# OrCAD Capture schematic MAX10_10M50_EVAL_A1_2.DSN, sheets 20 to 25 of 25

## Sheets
20 Hot Swap and Power 3.3 V: size A3
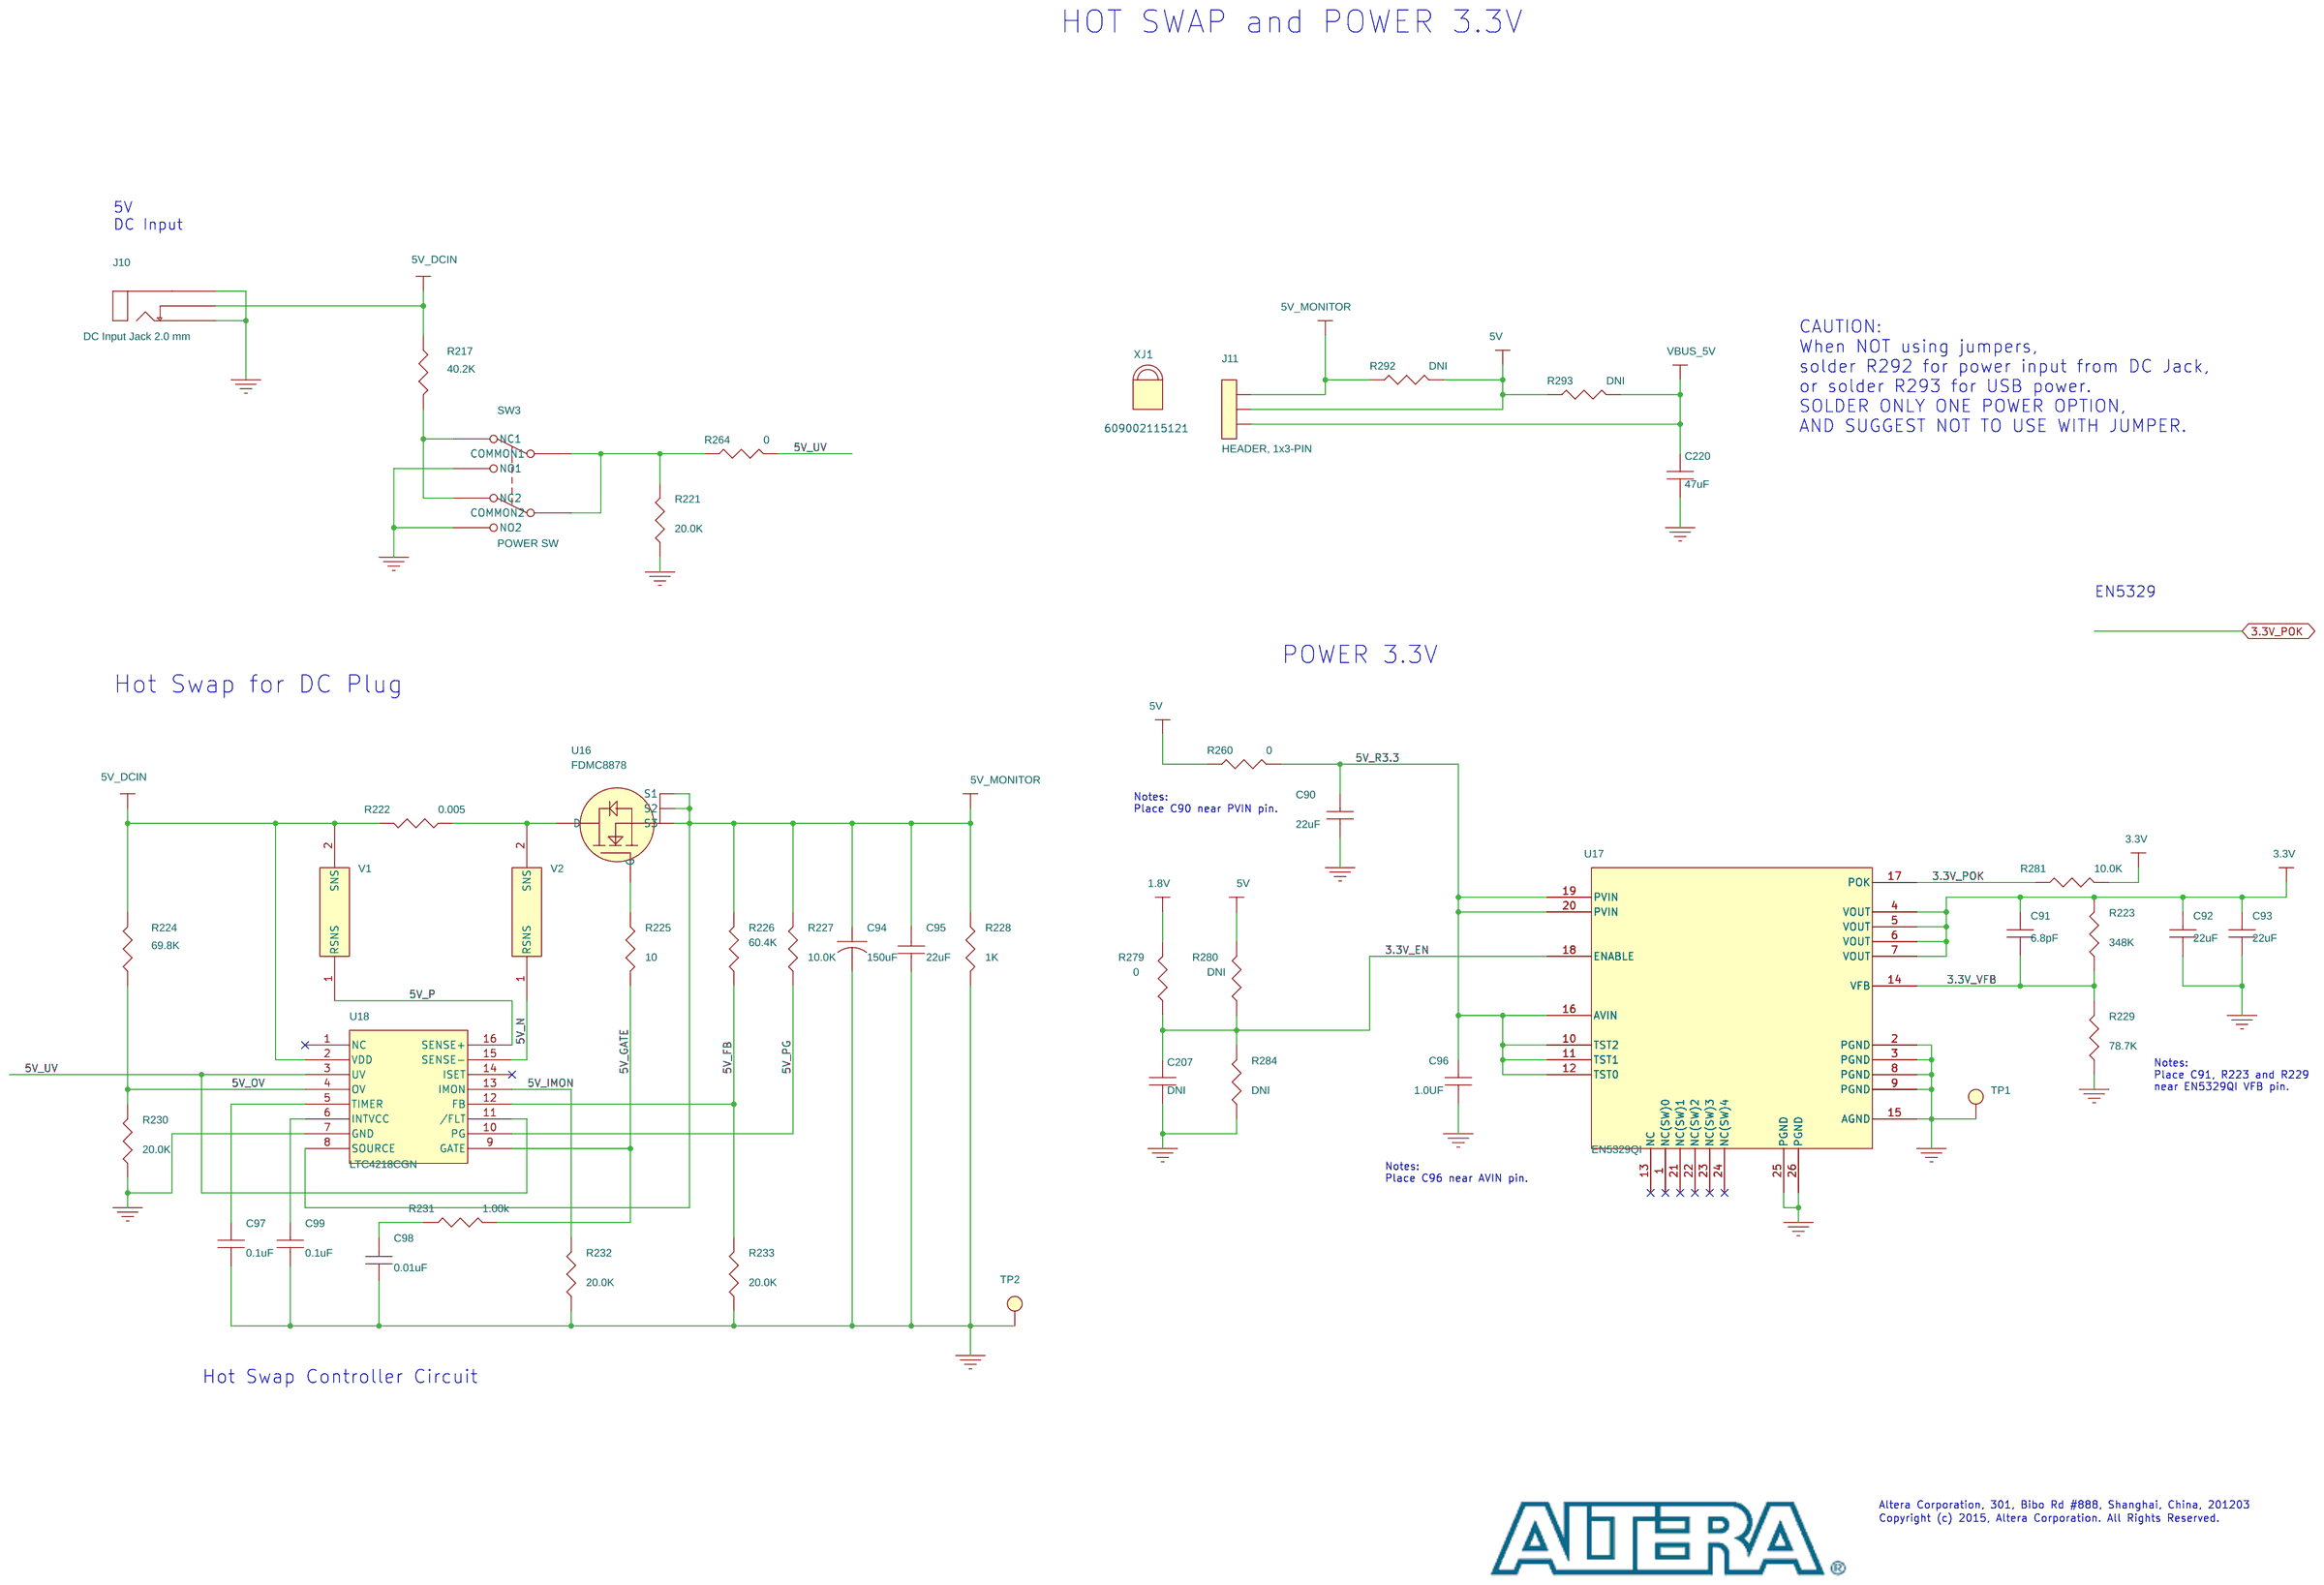
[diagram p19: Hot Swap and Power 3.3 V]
21 Power 2.5 V & 1.8V: size A3
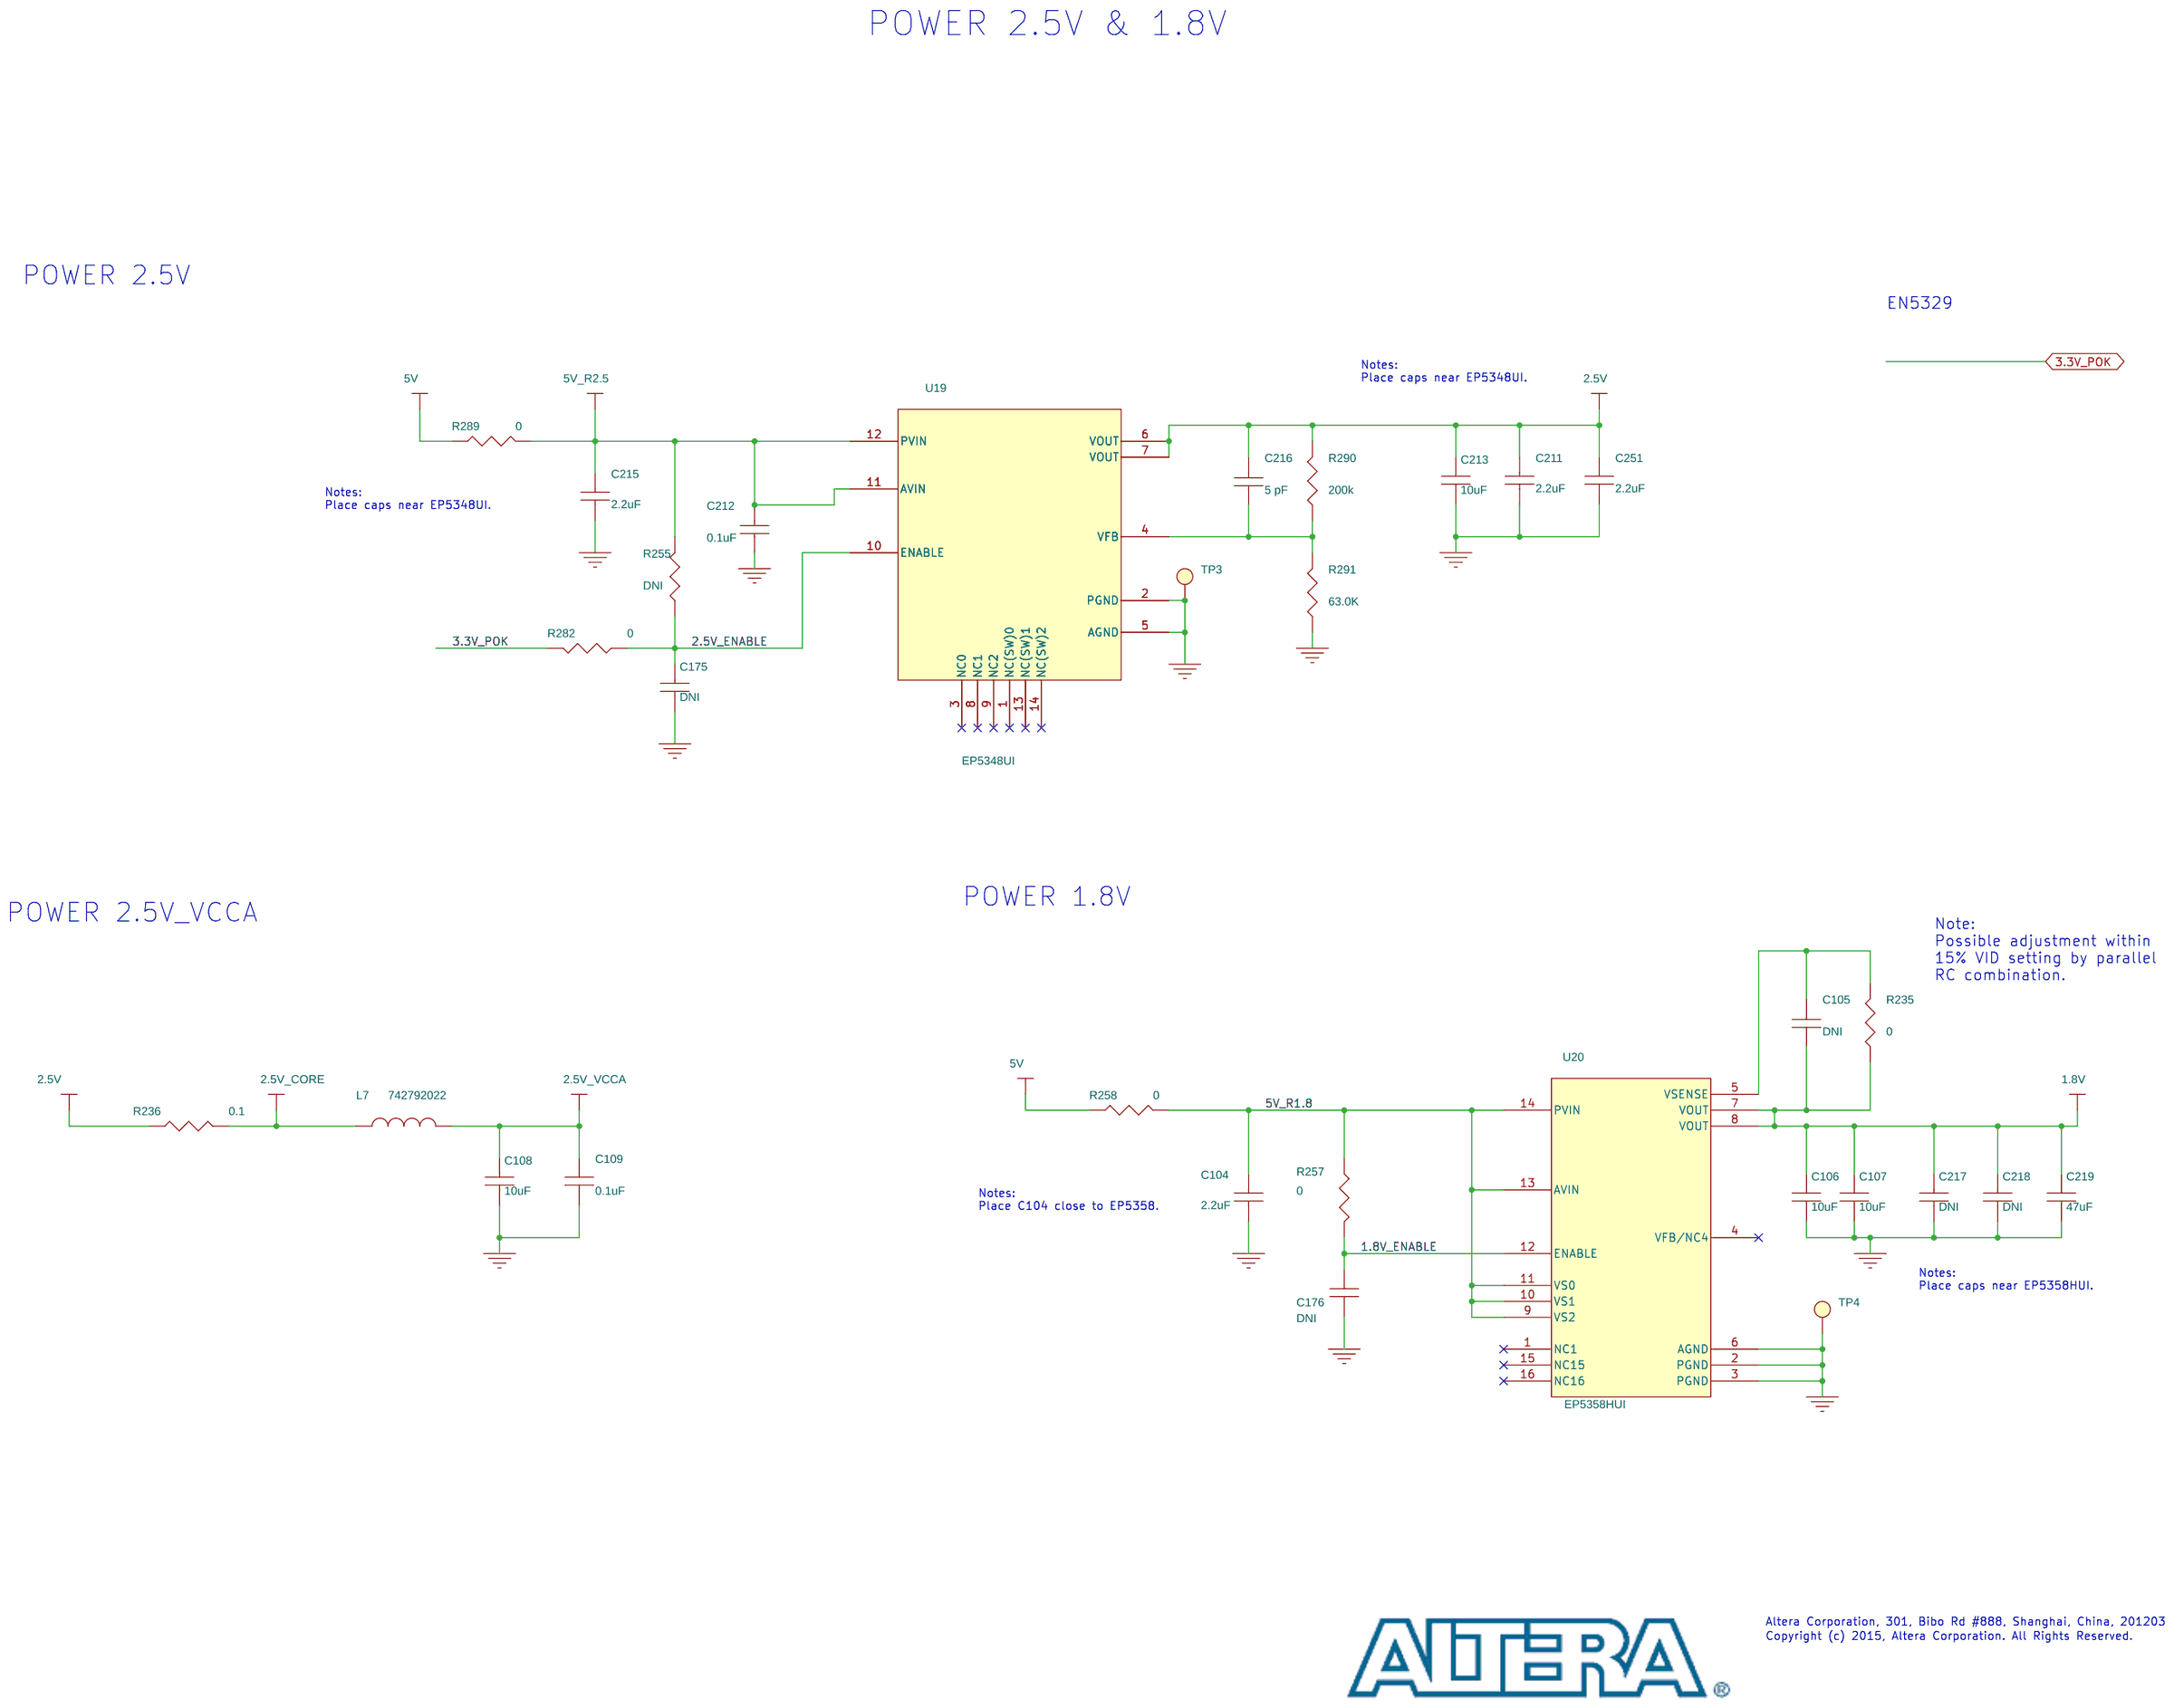
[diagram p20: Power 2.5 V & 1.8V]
22 Power 1.2V: size A3
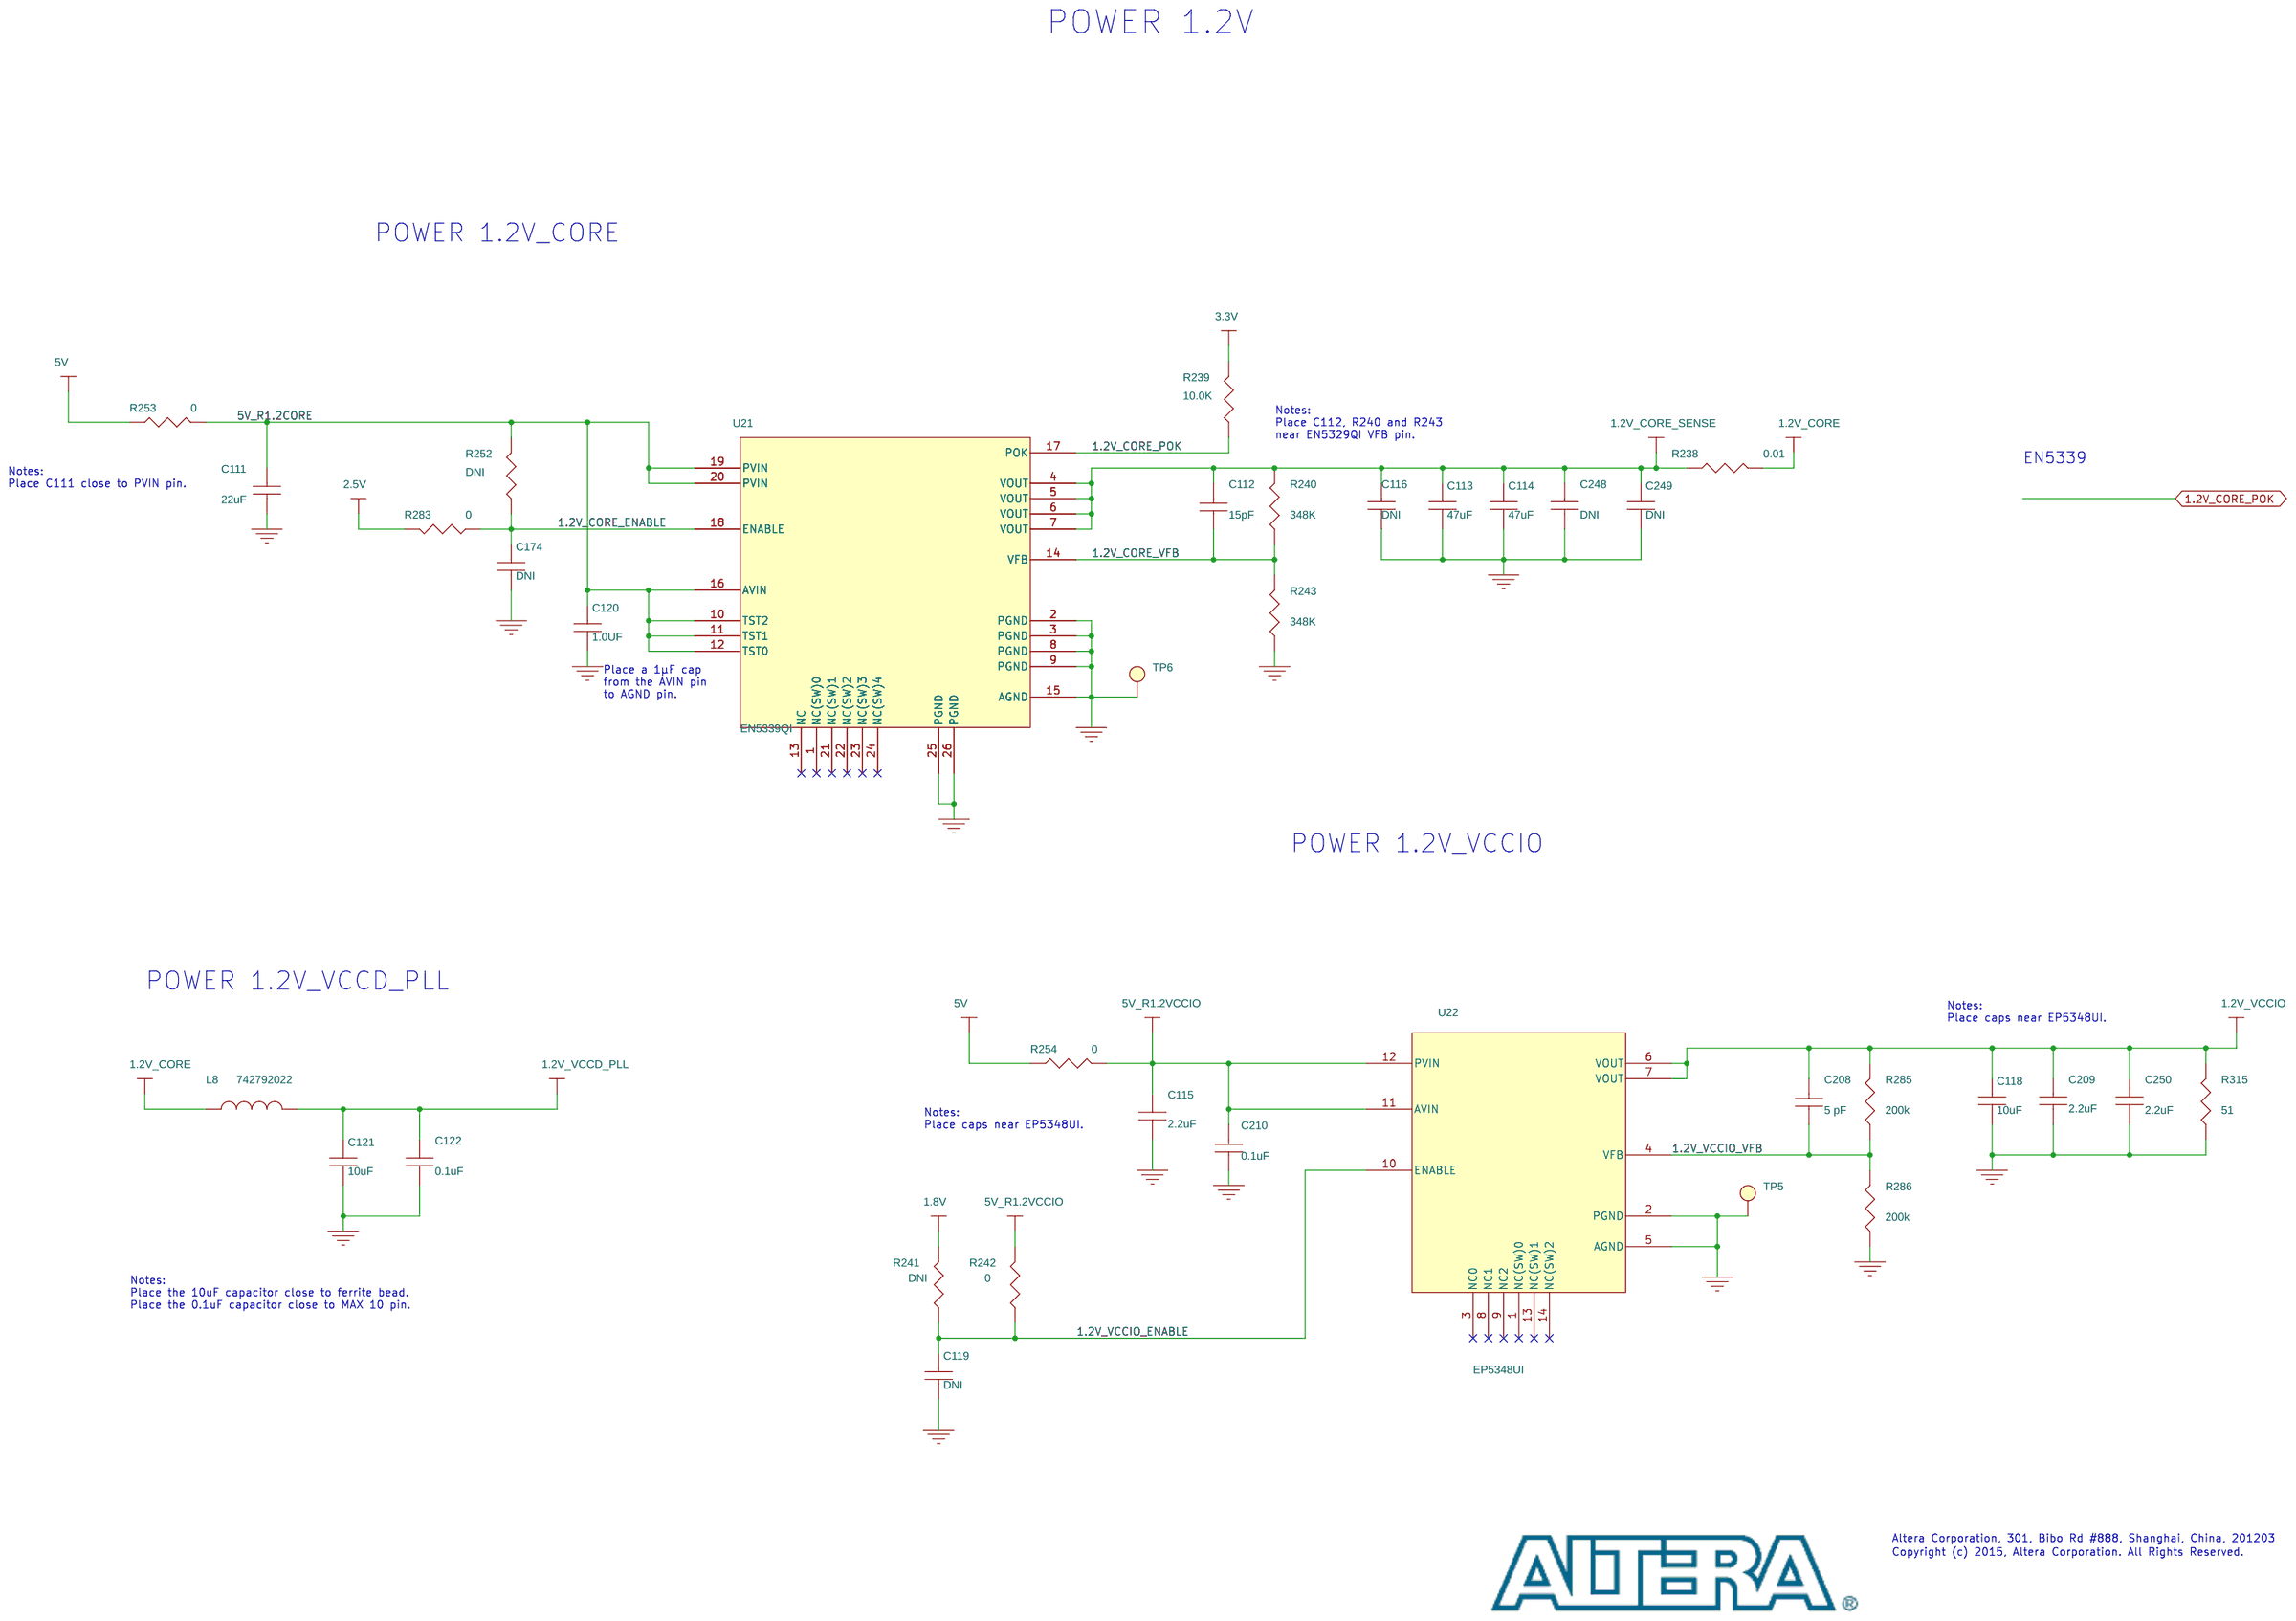
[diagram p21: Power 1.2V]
23 MAX 10 Power & Ground: size A3
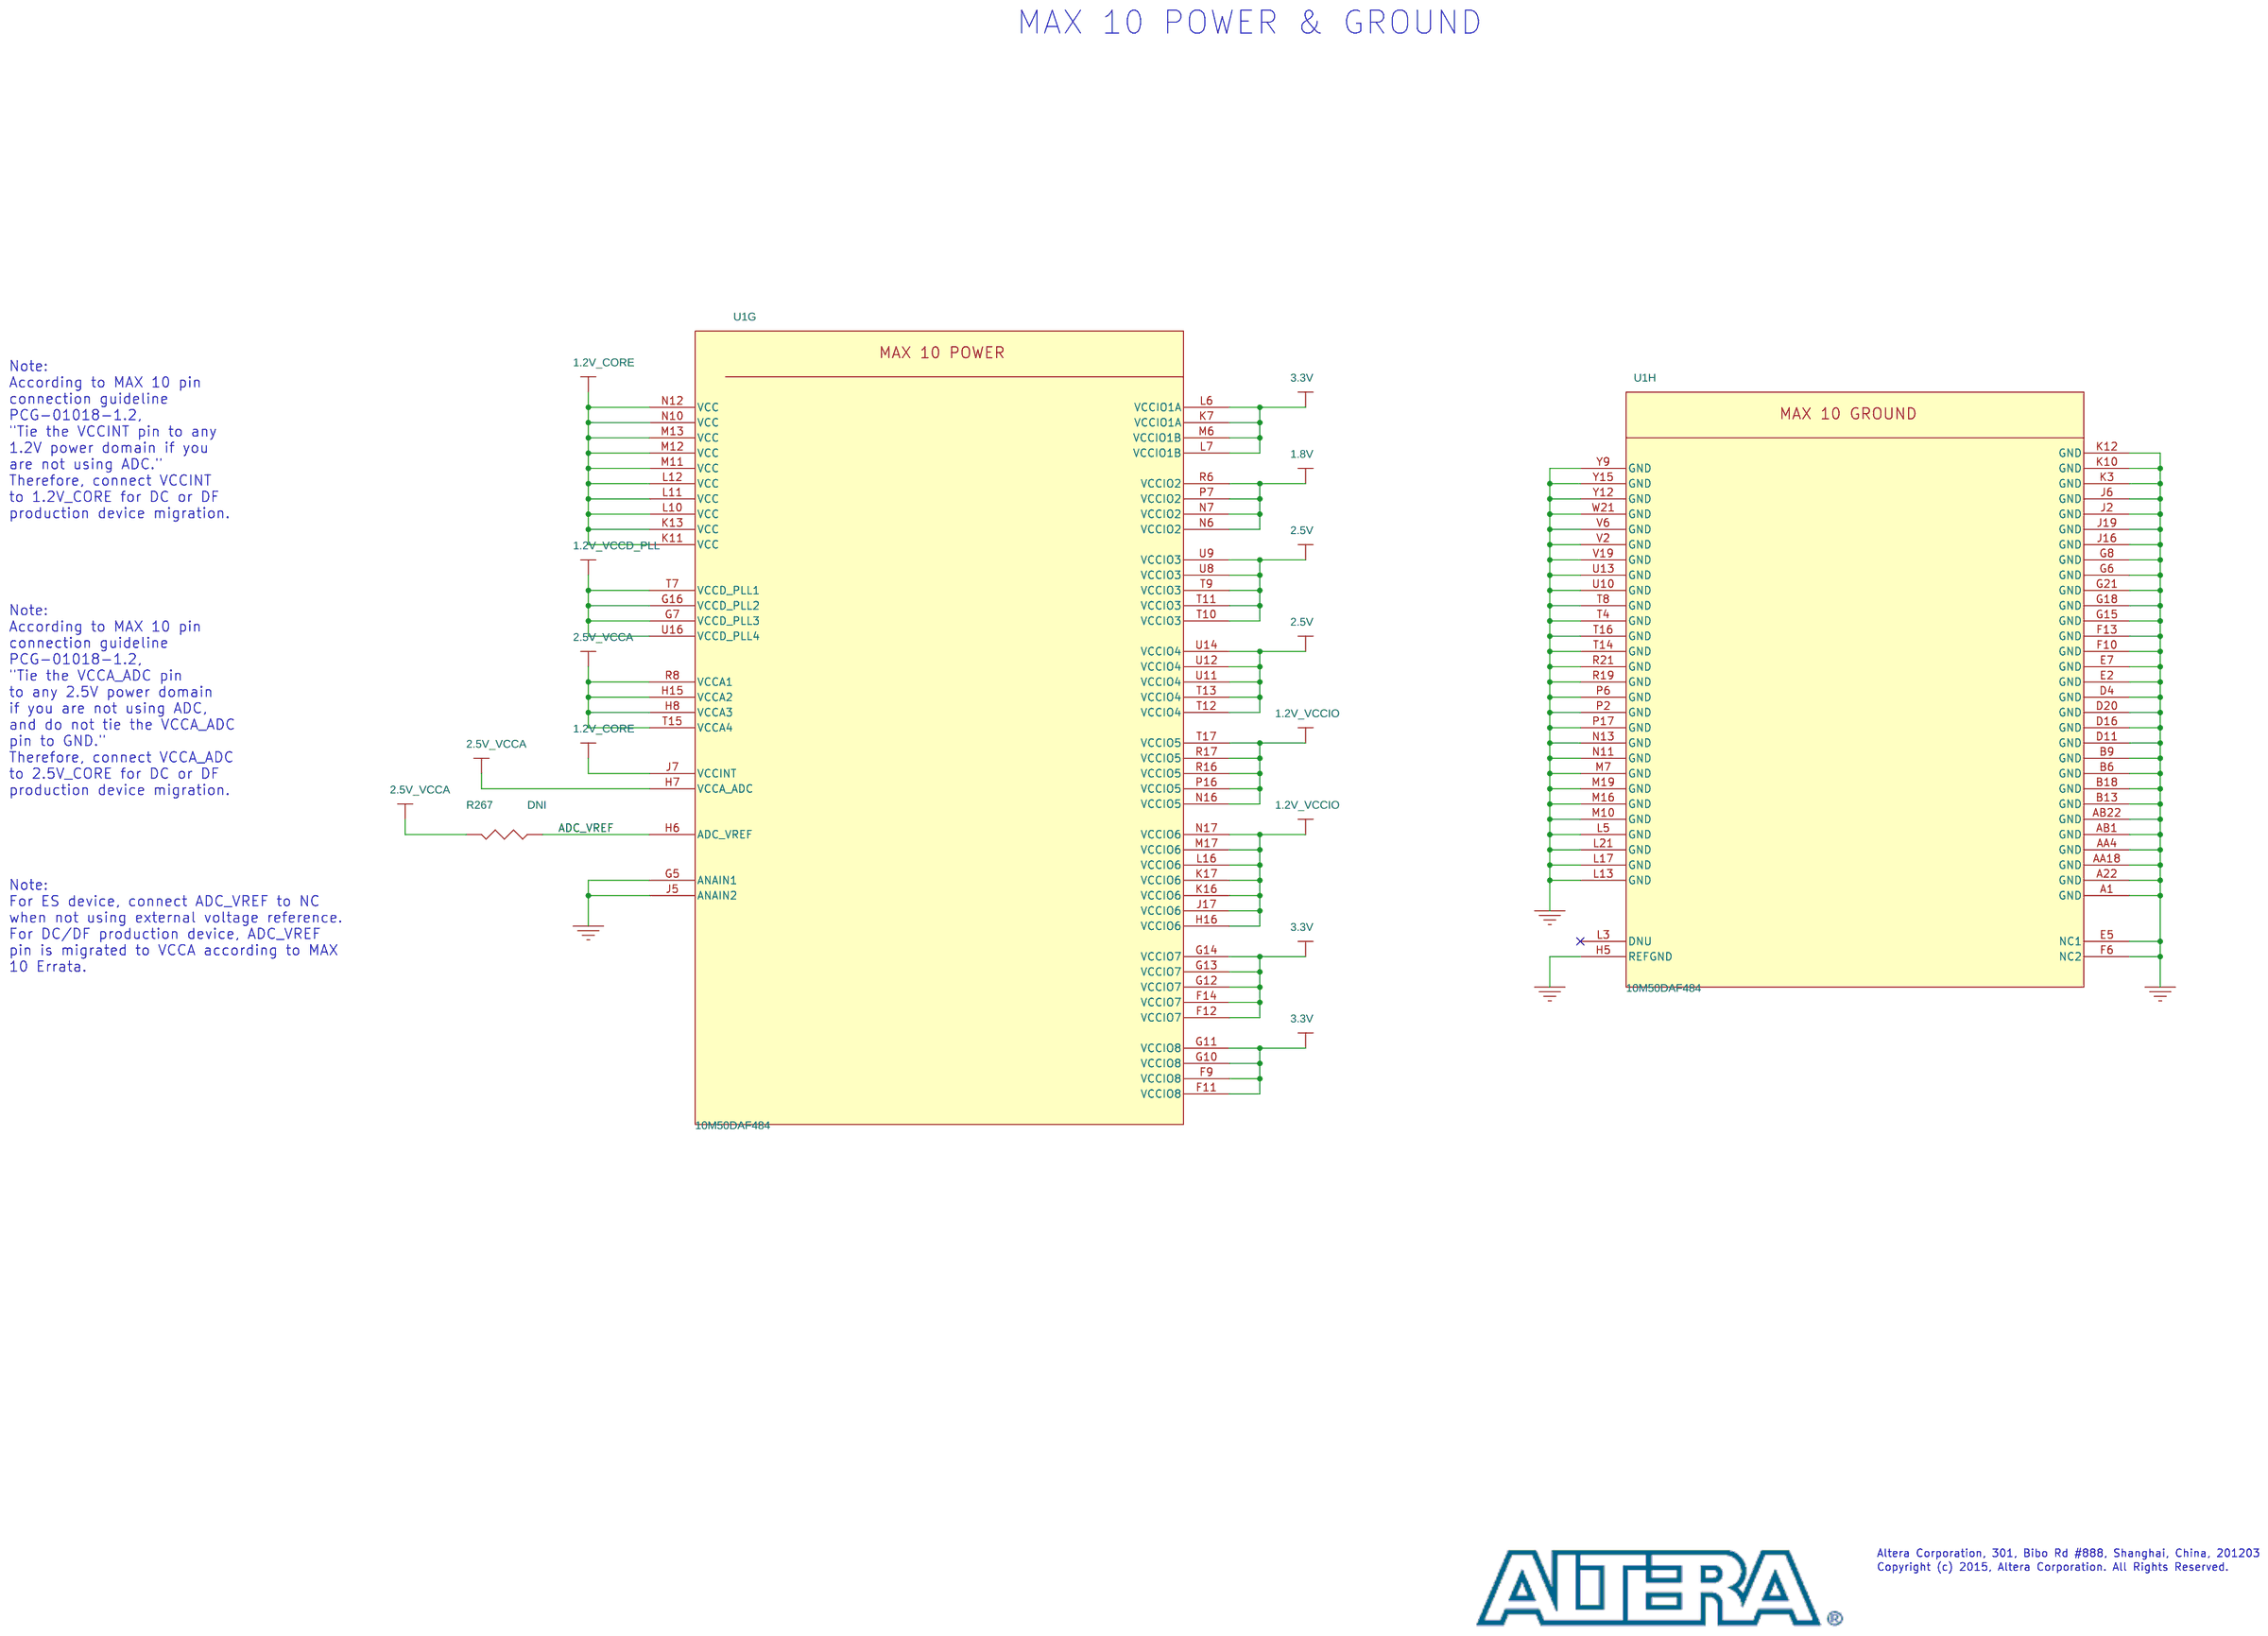
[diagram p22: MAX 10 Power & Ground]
24 Decoupling: size A3
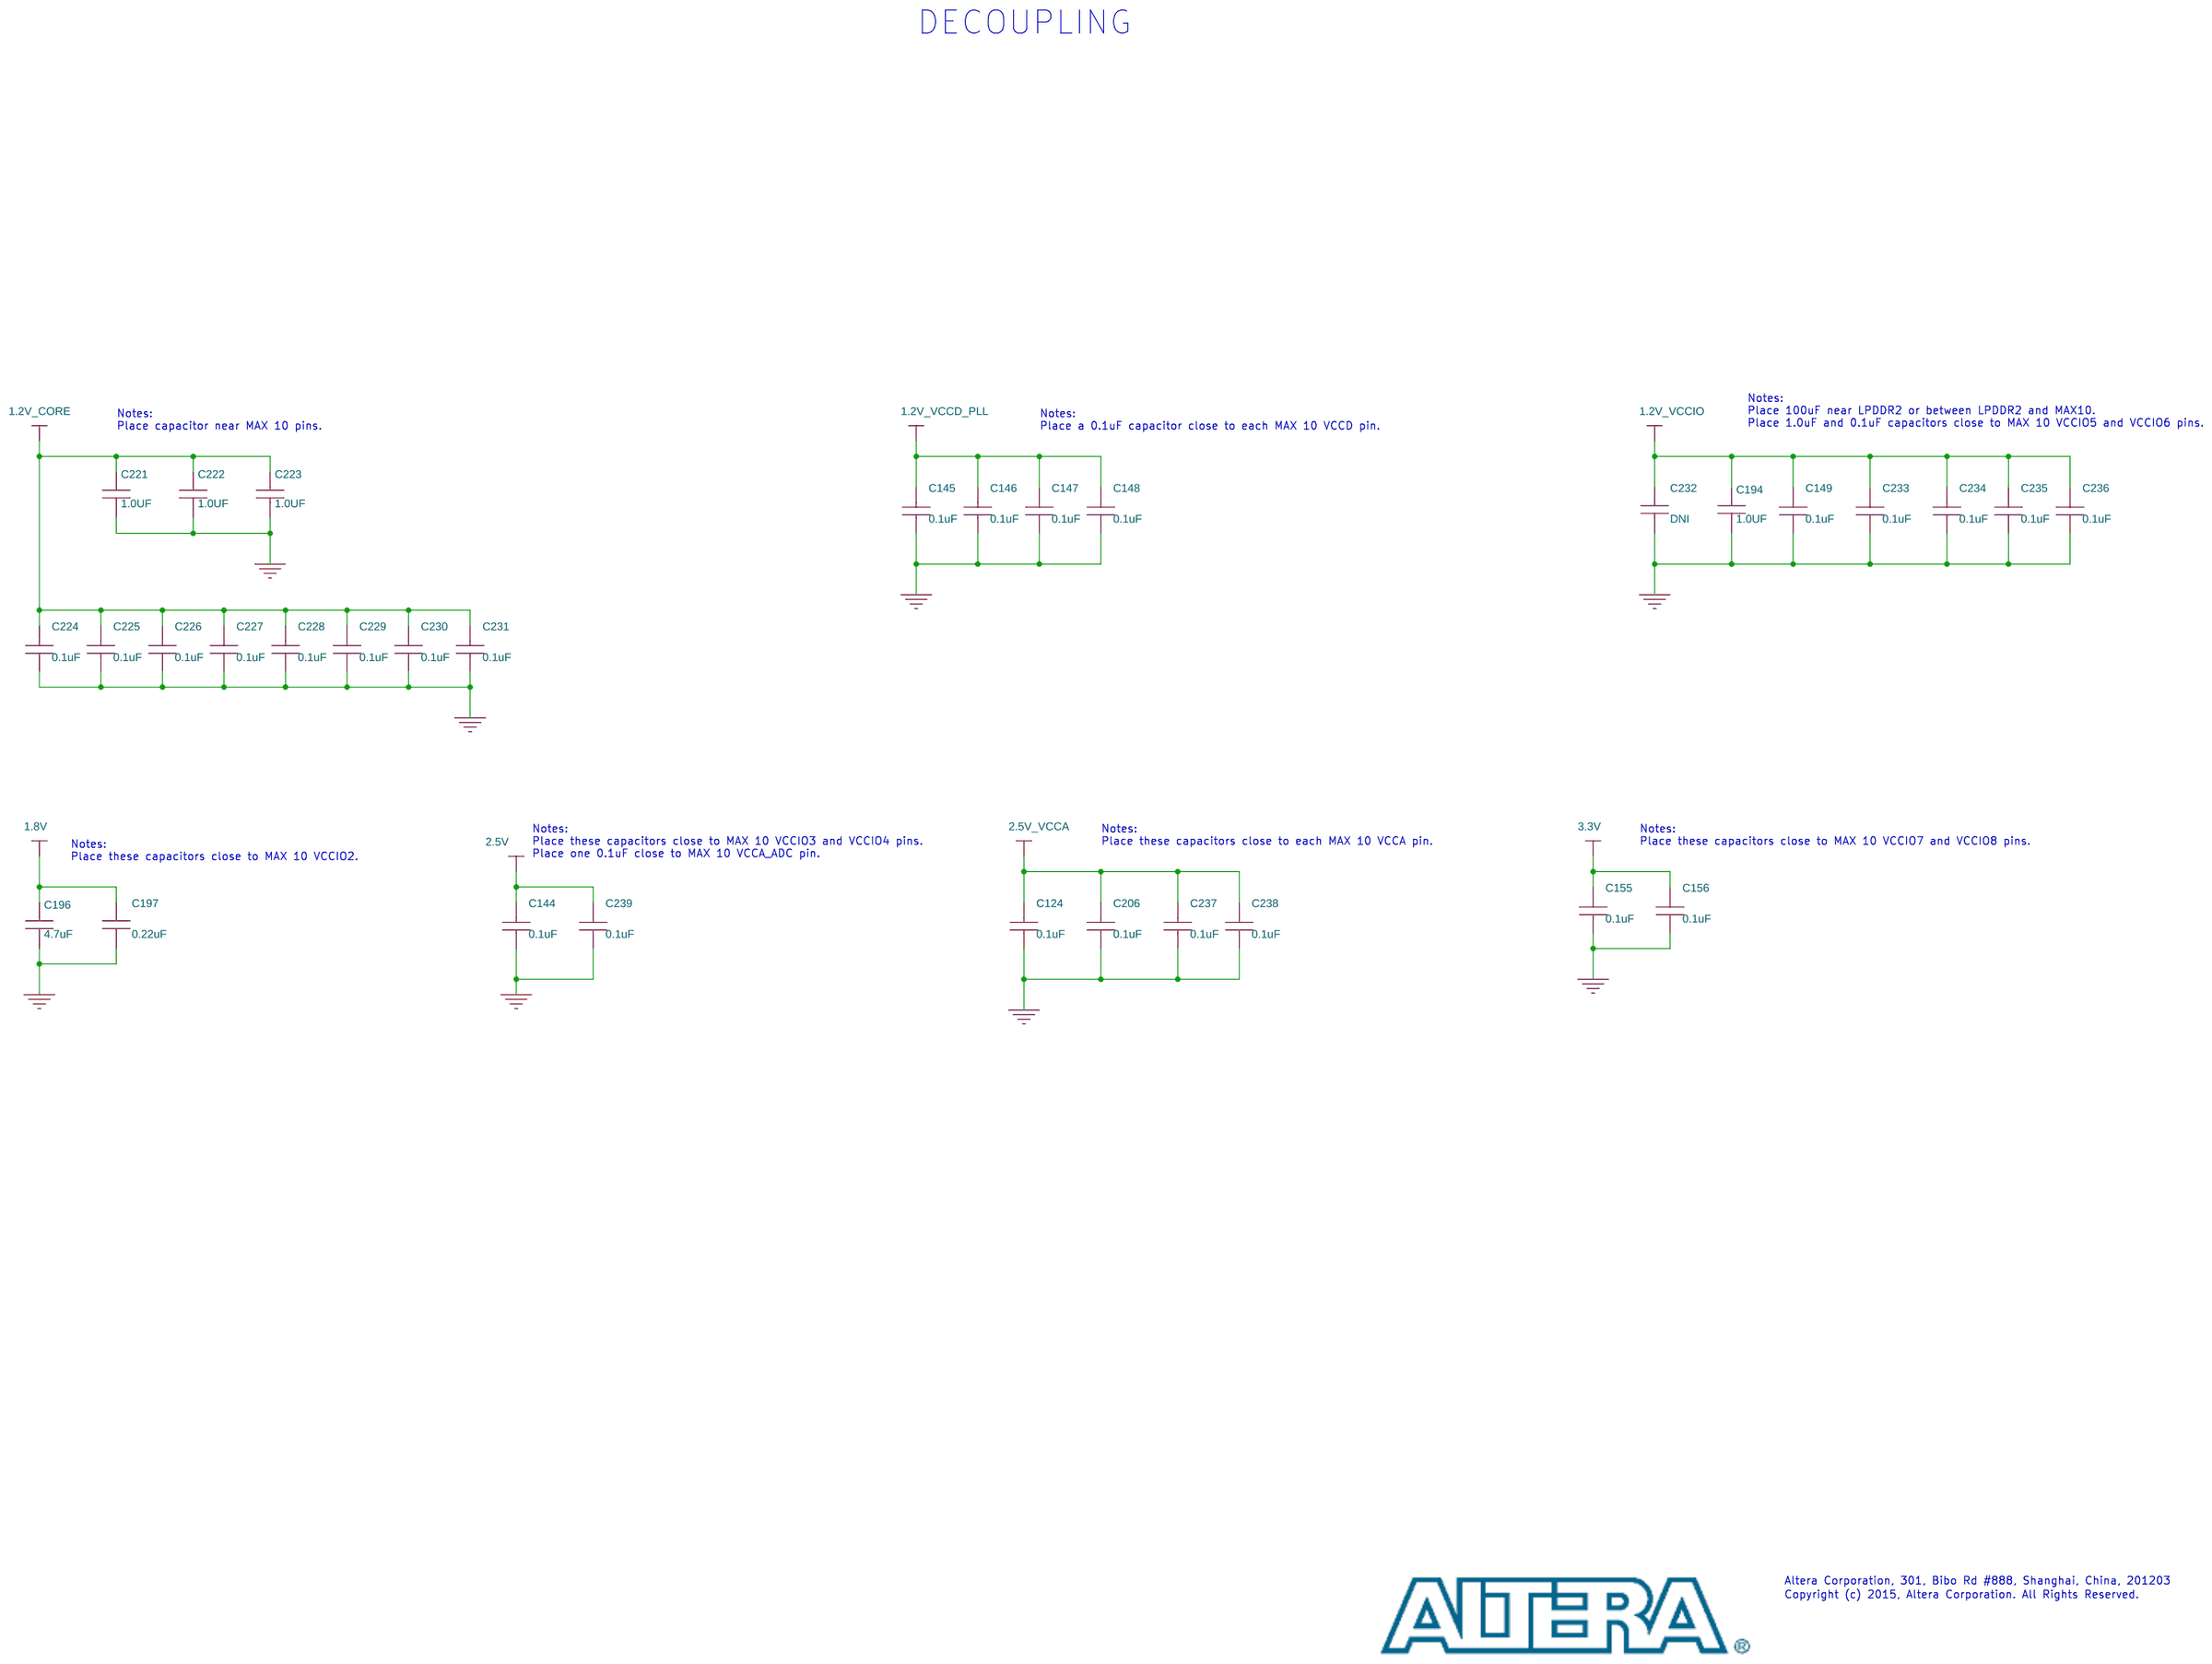
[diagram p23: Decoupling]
25 QSPI Flash: size A3
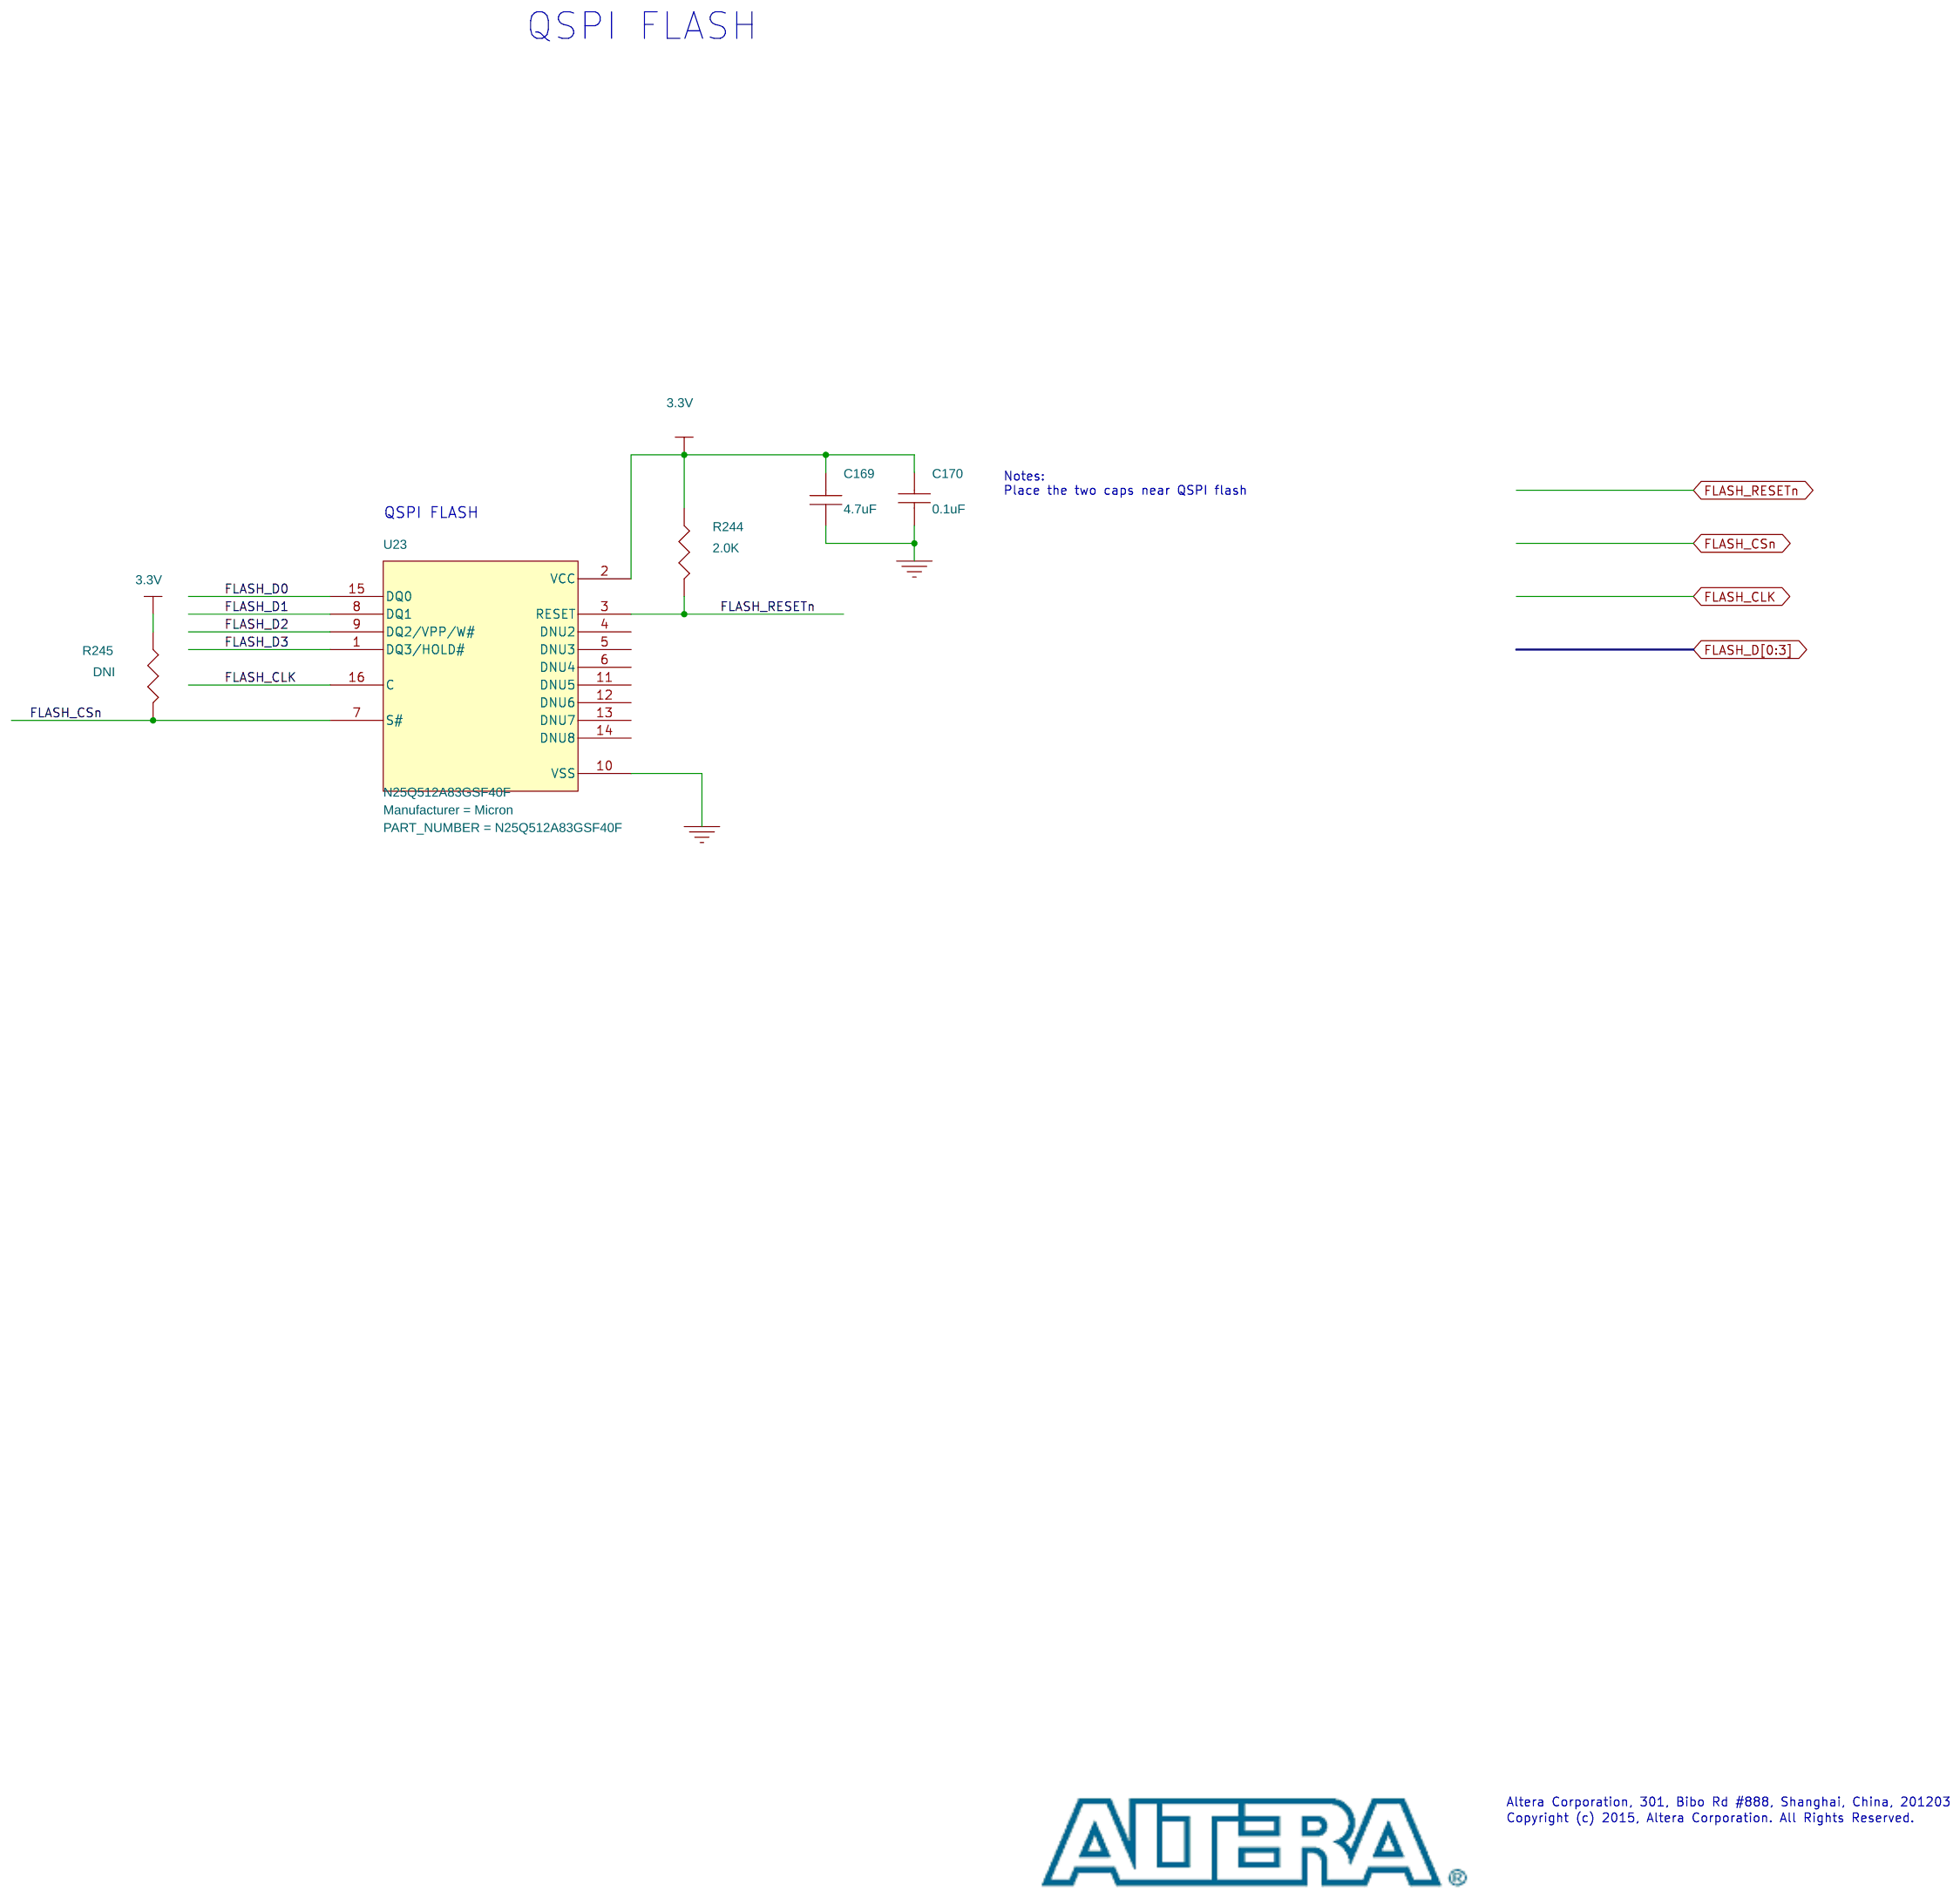
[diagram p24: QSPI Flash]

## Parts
sheet Decoupling
C124  0.1uF  [C0402_BGA]
C144  0.1uF  [C0402_BGA]
C145  0.1uF  [C0402_BGA]
C146  0.1uF  [C0402_BGA]
C147  0.1uF  [C0402_BGA]
C148  0.1uF  [C0402_BGA]
C149  0.1uF  [C0402_BGA]
C155  0.1uF  [C0402_BGA]
C156  0.1uF  [C0402_BGA]
C194  1.0UF  [C0402_BGA]
C196  4.7uF  [C0402_BGA]
C197  0.22uF  [0402]
C206  0.1uF  [C0402_BGA]
C221  1.0UF  [C0402_BGA]
C222  1.0UF  [C0402_BGA]
C223  1.0UF  [C0402_BGA]
C224  0.1uF  [C0402_BGA]
C225  0.1uF  [C0402_BGA]
C226  0.1uF  [C0402_BGA]
C227  0.1uF  [C0402_BGA]
C228  0.1uF  [C0402_BGA]
C229  0.1uF  [C0402_BGA]
C230  0.1uF  [C0402_BGA]
C231  0.1uF  [C0402_BGA]
C232  DNI  [1210]
C233  0.1uF  [C0402_BGA]
C234  0.1uF  [C0402_BGA]
C235  0.1uF  [C0402_BGA]
C236  0.1uF  [C0402_BGA]
C237  0.1uF  [C0402_BGA]
C238  0.1uF  [C0402_BGA]
C239  0.1uF  [C0402_BGA]
sheet Hot Swap and Power 3.3 V
C90  22uF  [0805]
C91  6.8pF  [0402]
C92  22uF  [0603]
C93  22uF  [0603]
C94  150uF  [7343P]
C95  22uF  [1206]
C96  1.0UF  [0402]
C97  0.1uF  [0402]
C98  0.01uF  [0402]
C99  0.1uF  [0402]
C207  DNI  [0402]
C220  47uF  [0805]
J10  DC Input Jack 2.0 mm  [JACK-DC_2MM]
J11  HEADER, 1x3-PIN  [CONN_TSW_103_07_L_S]
R217  40.2K  [0402]
R221  20.0K  [0402]
R222  0.005  [0805]
R223  348K  [0402]
R224  69.8K  [0402]
R225  10  [0402]
R226  60.4K  [0402]
R227  10.0K  [0402]
R228  1K  [0805]
R229  78.7K  [0402]
R230  20.0K  [0402]
R231  1.00k  [0402]
R232  20.0K  [0402]
R233  20.0K  [0402]
R260  0  [0603]
R264  0  [0402]
R279  0  [0402]
R280  DNI  [0402]
R281  10.0K  [0402]
R284  DNI  [0402]
R292  DNI  [0805]
R293  DNI  [0805]
SW3  POWER SW  [SW-PUSH-8x8]
TP1  T POINT R  [Test_Pad_SMT]
TP2  T POINT R  [Test_Pad_SMT]
U16  FDMC8878  [FDMC8878_VER2]
U17  EN5329QI  [EN5339QI]
U18  LTC4218CGN  [16-LEAD_PLASTIC_SSOP]
V1  SENSE_PAD  [SENSE]
V2  SENSE_PAD  [SENSE]
XJ1  609002115121  [NULL]
sheet MAX 10 Configuration
U1  10M50DAF484  [F484]  (sections A,B,C,D,E,F,G,H)
sheet MAX 10 Power & Ground
R267  DNI  [0402]
sheet Power 1.2V
C111  22uF  [0805]
C112  15pF  [0402]
C113  47uF  [0805]
C114  47uF  [0805]
C115  2.2uF  [0603]
C116  DNI  [0805]
C118  10uF  [0603]
C119  DNI  [0402]
C120  1.0UF  [0402]
C121  10uF  [0603]
C122  0.1uF  [0402]
C174  DNI  [0402]
C208  5 pF  [0402]
C209  2.2uF  [0603]
C210  0.1uF  [0402]
C248  DNI  [0603]
C249  DNI  [0402]
C250  2.2uF  [0603]
L8  742792022  [0805]
R238  0.01  [0805]
R239  10.0K  [0402]
R240  348K  [0402]
R241  DNI  [0402]
R242  0  [0402]
R243  348K  [0402]
R252  DNI  [0402]
R253  0  [0603]
R254  0  [0603]
R283  0  [0402]
R285  200k  [0402]
R286  200k  [0402]
R315  51  [0603]
TP5  T POINT R  [Test_Pad_SMT]
TP6  T POINT R  [Test_Pad_SMT]
U21  EN5339QI  [EN5339QI]
U22  EP5348UI  [EP5348UI]
sheet Power 2.5 V & 1.8V
C104  2.2uF  [0603]
C105  DNI  [0402]
C106  10uF  [0805]
C107  10uF  [0603]
C108  10uF  [0603]
C109  0.1uF  [0402]
C175  DNI  [0402]
C176  DNI  [0402]
C211  2.2uF  [0603]
C212  0.1uF  [0402]
C213  10uF  [0603]
C215  2.2uF  [0603]
C216  5 pF  [0402]
C217  DNI  [0805]
C218  DNI  [0805]
C219  47uF  [0805]
C251  2.2uF  [0402]
L7  742792022  [0805]
R235  0  [0402]
R236  0.1  [0805]
R255  DNI  [0402]
R257  0  [0402]
R258  0  [0603]
R282  0  [0402]
R289  0  [0603]
R290  200k  [0402]
R291  63.0K  [0402]
TP3  T POINT R  [Test_Pad_SMT]
TP4  T POINT R  [Test_Pad_SMT]
U19  EP5348UI  [EP5348UI]
U20  EP5358HUI  [uQFN16]
sheet QSPI Flash
C169  4.7uF  [0402]
C170  0.1uF  [0402]
R244  2.0K  [0402]
R245  DNI  [0402]
U23  N25Q512A83GSF40F  [SO16_WIDE]

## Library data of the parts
C109 C122 C124 C144-C149 C155 C156 C170 C206 C210 C212 C224-C231 C233-C239 = Cap_0.1UF_+_-10%_10V_0402
C96 C119 C120 C174-C176 C194 C207 C221-C223 C249 = CAP_1.0UF_10%_10V_0402
C169 C196 = Cap_4.7uF_10%_6.3V_X5R_0402
C197 = Cap_0.1UF_+_-10%_10V_0402: CAP CER 0.22UF 16V 10% X5R 0402; Item Num: P03-17803R; Manufacturer Part Num: ECJ-0EB1C224K
C232 = CAP: CAP - CER, 100UF, 6.3V, +/-20%, X5R, 1210 SMD; Dielectric: X5R; Item Num: P03-16332R; Manufacturer: Panasonic; Manufacturer Part Num: ECJ-4YB0J107M; RoHS Compliant: Yes; Tolerance: 20%; Working Voltage: 6.3V
C90 C111 C116 = Cap_0.1UF_+_-10%_10V_0402: CAP - CER 22UF, 10V, 20%, X5R, 0805; Item Num: P03-17685R; Manufacturer: TDK Electronics; Manufacturer Part Num: C2012X5R1A226M085AC
C91 = Cap_0.1UF_+_-10%_10V_0402: CAP - CER 6.8PF 25V NP0 0402; Item Num: P03-17804R; Manufacturer: Murata; Manufacturer Part Num: GRM1555C1E6R8CA01D
C92 C93 = Cap_0.1UF_+_-10%_10V_0402: CAP, CERAMIC, 22uF, 0603 MLCC, 20%, 6.3VDC, X5R; Item Num: P03-17794R; Manufacturer: Murata; Manufacturer Part Num: GRM188R60J226MEA0
C94 = PCAP: CAP - TANT POLYMER,150UF,16V,50MOHM ESR20%, 7343*1.8MM; Item Num: P03-17713R; LIFECYCLE_PHASE: Active; Lead Free Status: Lead Free; MFR_LIFECYCLE: Active; Manufacturer: Panasonic; Manufacturer Part Num: 16TQC150MYF; Num Pins: 2; PART_SUBCLASS: CAPACITORS; RATED_VOLTAGE: 16V; RoHS Compliant: RoHS Compliant; TOLERANCE: +/-20%
C95 = CAP: CAP - CER, 22UF, 25V, 10%, X5R, 1206; Item Num: P03-17640R; Lead Free Status: Yes; Manufacturer: Murata; Manufacturer Part Num: GRM31CR61E226KE15L; Num Pins: 2; Part Class: Capacitors; Price: 0; RoHS Compliant: Yes
C97 C99 = CAP: CAP - CERAMIC,  0.1UF 0402 25VDC Y5V; Dielectric: Y5V; Item Num: P03-15057R; LIFECYCLE_PHASE: Active; Lead Free Status: Lead Free; MFR_LIFECYCLE: Active; Manufacturer: Murata; Manufacturer Part Num: GRM155F51E104ZA01D; Num Pins: 2; PART_SUBCLASS: CAPACITORS; Part Class: CAPACITORS; RATED_VOLTAGE: 25V; RoHS Compliant: RoHS Compliant; Tolerance: +80%/-20%
C98 = CAP: CAP - CER, 10NF, 50V, +/-10%, X7R, 0402 SMD; Dielectric: X5R; Item Num: P03-16318R; Lead Free Status: Yes; Manufacturer: Murata; Manufacturer Part Num: GRM155R71H103KA88D; Manufacturer's Part No.: GRM155R71H103KA88D; Num Pins: 2; Part Class: CAPACITORS; Price: 0.07; RoHS Compliant: Yes; Tolerance: 10%
C113 C114 C219 C220 = CAP: CAP - CER 47UF, 10V, 20%, X5R, +/-20%, 0805; AGILE_LINK: http://sj-agile9app/Agile/PLMServlet?action=OpenEmailObject&classid=10000&objid=260383822; Item Num: P03-17686R; LIFECYCLE_PHASE: Active; Lead Free Status: Lead Free; MFR_LIFECYCLE: Active; Manufacturer: TDK Electronics; Manufacturer Part Num: C2012X5R1A476M125AC; Num Pins: 2; PART_SUBCLASS: CAPACITORS; RATED_VOLTAGE: 10V; RoHS Compliant: RoHS Compliant; TOLERANCE: +/-20%
J10 = Jack-DC: DC JACK , 3 PIN, BLACK, 9V, Size:8.85*14.4*10.7 mm; Item Num: P23-36933R; Manufacturer: LEAMAX; Manufacturer Part Num: 32753PA; Package: DIP; Supplier: LEAMAX; Supplier_Prt: 32753PA; Terasic_Prt: M0207; Type: Jack
J11 = HEADER,_1x3-PIN: CONN HEADER 3 POS 2.54MM, THROUGH HOLE; Item Num: P23-38703R; Manufacturer: Wurth Electronics; Manufacturer Part Num: 61300311121
R217 = RESISTOR: RES - 40.2K OHM, 1/16W, 1%, 0402, SMD; Item Num: P02-15887R; LIFECYCLE_PHASE: Active; Lead Free Status: No; MFR_LIFECYCLE: Active; Manufacturer: Panasonic; Manufacturer Part Num: ERJ-2RKF4022x; Num Pins: 2; PART_SUBCLASS: RESISTORS; POWER: 1/16W; RoHS Compliant: Yes; TOLERANCE: +/-1%
R221 R230 R232 R233 R255 R284 = RESISTOR: RES 20.0K OHM 1/16W 1% 0402 SMD; Item Num: P02-14071R; Lead Free Status: Yes; Manufacturer: Panasonic; Manufacturer Part Num: ERJ-2RKF2002X; Num Pins: 2; Part Class: RESISTORS; RoHS Compliant: Yes
R222 = RESISTOR: RES 0.005 OHM 1% 1/2W 0805; AGILE_LINK: http://sj-agile9app/Agile/PLMServlet?action=OpenEmailObject&classid=10000&objid=112752009; Item Num: P02-17733R; LIFECYCLE_PHASE: Active; Lead Free Status: Yes; Manufacturer: Panasonic; Manufacturer Part Num: ERJ6LWFR005V; Num Pins: 2; PART_SUBCLASS: RESISTORS; POWER: 1/2W; TOLERANCE: +/-1%
R223 R240 R243 = RESISTOR: RES 348K OHM 1/10W 1% 0402 SMD; Item Num: P02-17553R; Lead Free Status: Yes; Manufacturer: Panasonic; Manufacturer Part Num: ERJ-2RKF3483X; Num Pins: 2; Part Class: RESISTORS; RoHS Compliant: Yes
R224 = RES_16.5K_OHM_1_10W_1%_0402: RES - 69.8K OHM, 1/10W, 1%, 0402, SMD; Item Num: P02-17462R; Manufacturer Part Num: ERJ-2RKF6982x
R225 = RES_10_OHM_1.0%_1_16W_0402: RES, 10 OHMS, 1.0%, 1/10W, 0402
R226 = RES_16.5K_OHM_1_10W_1%_0402: RES - 60.4K OHM, 1/16W, 1%, 0402, SMD; Item Num: P02-17461R; Manufacturer Part Num: ERJ-2RKF6042X
R227 R239 R281 = RESISTOR: RES,10.0K OHMS,1.0%,1/16W, 0402; AGILE_LINK: http://sj-agile9app/Agile/PLMServlet?action=OpenEmailObject&classid=10000&objid=146548997; Item Num: P02-11364R; LIFECYCLE_PHASE: Active; Lead Free Status: No; MFR_LIFECYCLE: Active; Manufacturer: Panasonic; Manufacturer Part Num: ERJ-2RKF1002X; Num Pins: 2; PART_SUBCLASS: RESISTORS; POWER: 1/16W; RoHS Compliant: Yes; TOLERANCE: +/-1%
R228 = RESISTOR: RES 1K OHM 1/4W 5% 0805 SMD; Item Num: P02-17649R; Lead Free Status: Yes; Manufacturer: Panasonic; Manufacturer Part Num: ERJ-T06J102V; Mfr Prt #: ERJ-T06J102V; Num Pins: 2; Part Class: RESISTORS; RoHS Compliant: Yes
R229 = RESISTOR: RES, 78.7K OHM 1/16W 1% 0402 SMD; Item Num: P02-14159R; Lead Free Status: Yes; Manufacturer: Panasonic; Manufacturer Part Num: ERJ-2RKF7872X; Num Pins: 2; Part Class: RESISTORS; RoHS Compliant: Yes
R231 = RESISTOR: RES,1.00K OHMS,1.0%,1/16W,0402; Item Num: P02-11372R; Lead Free Status: No; Manufacturer: Panasonic; Manufacturer Part Num: ERJ-2RKF1001X; Num Pins: 2; Part Class: Resistors
R253 R254 R258 R260 R289 = RESISTOR: RES - 0 OHM, 5% 0603 1/10W; Altera Part No.: P02-14007R; Item Num: P02-14007R; Lead Free Status: No; Manufacturer: Panasonic; Manufacturer Part Num: ERJ-3GEY0R00V; Num Pins: 2; Part Class: RESISTORS; RoHS Compliant: Yes; Tolerance: 5%
R235 R242 R257 R264 R279 R282 R283 = RESISTOR: RES ZERO OHM 1/16W 5% 0402 SMD; Altera Part No.: P02-14020R; Item Num: P02-14020R; Lead Free Status: No; Manufacturer: Panasonic; Manufacturer Part Num: ERJ-2GE0R00X; Num Pins: 2; Part Class: RESISTORS; RoHS Compliant: Yes; Tolerance: 5%
R241 R267 R280 = RESISTOR: RES ZERO OHM 1/16W 5% 0402 SMD; Altera Part No.: P02-14020R; Item Num: P02-14020R; Lead Free Status: No; Manufacturer: Panasonic; Manufacturer Part Num: ERJ-2GE0R00X; Num Pins: 2; Part Class: RESISTORS; Price: 0; RoHS Compliant: Yes; Tolerance: 5%
R292 R293 = RESISTOR: RES, 0 Ohms, 5.0%, 1/8W, 0805; Altera Part No.: P02-11383R; Item Num: P02-11383R; Lead Free Status: Yes; Manufacturer: Panasonic; Manufacturer Part Num: ERJ-6GEY0R00V; Num Pins: 2; Part Class: RESISTORS; Price: 0; RoHS Compliant: Yes; Tolerance: 5%
SW3 = SW-PUSH_3: Push SW, 8*8; Item Num: P23-37294R; Manufacturer: SANHUNG; Manufacturer Part Num: PS-22E80L; Package: DIP; Supplier: 把Щ; Supplier_Prt: PS-22E80L; Terasic_Prt: M0494; Type: Switch
TP1 TP2 = T_POINT_R: Test Point SMT
U16 = FDMC8878_VER2: MOSFET - N-CHANNEL PWR TRENCH 16.5A 30V 14MOHM POWER33; Item Num: P18-31175R; Manufacturer: Fairchild Semiconductor
U17 = EN5329_5339QI_0: 2A LOW PROFILE SYNC BUCK DC-DC, VIN 2.4 - 5.5V, 24-QFN; Item Num: P05-18754R; Manufacturer: Enpirion; Part Class: Regulators; RoHS Compliant: Yes
U18 = LTC4218CGN: HOT SWAP CONTROLLER; Item Num: P01-17923R; Manufacturer: Linear Technology
V1 V2 = SENSE_PAD: Item Num: P23-SENSE; Manufacturer: NONE; Manufacturer Part Num: NONE
XJ1 = SHUNT: 2.54MM JUMPER WITH TEST POINT AND PULLBACK; ID: 213681; Item Num: P23-38704R; Lead Free Status: No; Manufacturer: Wurth Electronics; Num Pins: 2; Part Class: Jumper; RoHS Compliant: Yes
U1 = 10M50DAF484_v2.0_4.5: IC - MAX 10 FPGA, 10M50DAF484C6GES, 50K LES, F484 BGA, LEADFREE, ENGINEERING SAMPLE; Item Num: P01-17977R; Manufacturer: Altera Corporation; Manufacturer Part Num: 10M50DAF484C6GES; Part Class: Regulators; RoHS Compliant: Yes
C112 = CAP: CAP - CER, 15PF, 50V, +/-5%, C0G, 0402 SMD; Item Num: P03-16322R; LIFECYCLE_PHASE: Active; Lead Free Status: Lead Free; MFR_LIFECYCLE: Active; Manufacturer: Panasonic; Manufacturer Part Num: ECJ-0EC1H150J; Num Pins: 2; PACKAGING: Tape & Reel (TR); PART_SUBCLASS: CAPACITORS; RATED_VOLTAGE: 50V; RoHS Compliant: RoHS Compliant; Tolerance: +/-5%
C104 C115 C209 C211 C215 C250 = CAP: CAP, CERAMIC, 2.2UF, 0603, 10%, 10VDC, X5R; AGILE_LINK: http://sj-agile9app/Agile/PLMServlet?action=OpenEmailObject&classid=10000&objid=256999866; Item Num: P03-15017R; LIFECYCLE_PHASE: Active; Lead Free Status: Lead Free; MFR_LIFECYCLE: Active; Manufacturer: Panasonic; Manufacturer Part Num: ECJ-1VB1A225M; Num Pins: 2; PART_SUBCLASS: CAPACITORS; RATED_VOLTAGE: 10V; RoHS Compliant: RoHS Compliant; Supplier Part Num: 490-1545-1-ND; TOLERANCE: +/-10%
C107 C108 C118 C121 C213 = CAP: CAP - CERAMIC, 10UF, 6.3V, +/-20%, X5R, 0603 SMD; AGILE_LINK: http://sj-agile9app/Agile/PLMServlet?action=OpenEmailObject&classid=10000&objid=260383822; Item Num: P03-16323R; LIFECYCLE_PHASE: Active; Lead Free Status: Lead Free; MFR_LIFECYCLE: Active; Manufacturer: Panasonic; Manufacturer Part Num: ECJ-1VB0J106M; Num Pins: 2; PART_SUBCLASS: CAPACITORS; RATED_VOLTAGE: 6.3V; RoHS Compliant: RoHS Compliant; TOLERANCE: +/-20%
C105 C208 C216 = CAP: CAP - CER 5PF, 50V, +/-0.25PF, NP0, 0402; Item Num: P03-17675R; Lead Free Status: Yes; Manufacturer: Murata; Manufacturer Part Num: GRM1555C1H5R0CA01D; Num Pins: 2; Part Class: Capacitors; Price: 0; RoHS Compliant: Yes
C248 = CAP: CAP, CERAMIC, 2.2UF, 0603, 10%, 10VDC, X5R; AGILE_LINK: http://sj-agile9app/Agile/PLMServlet?action=OpenEmailObject&classid=10000&objid=256999866; CAPACITANCE: 2.2uF; Item Num: P03-15017R; LIFECYCLE_PHASE: Active; Lead Free Status: Lead Free; MFR_LIFECYCLE: Active; Manufacturer: Panasonic; Manufacturer Part Num: ECJ-1VB1A225M; Num Pins: 2; PART_SUBCLASS: CAPACITORS; RATED_VOLTAGE: 10V; RoHS Compliant: RoHS Compliant; Supplier Part Num: 490-1545-1-ND; TOLERANCE: +/-10%
L7 L8 = INDUCTOR: IND - FERRITE BEAD 220 OHM 2.0A 0805; Item Num: P04-17105R; Manufacturer: Wurth Elektronik
R238 = RESISTOR: RES  0.01 OHM 1% 1/2W 0805 SMD; Item Num: P02-17736R; Lead Free Status: Yes; Manufacturer: Panasonic; Manufacturer Part Num: ERJ6BWFR010V; Num Pins: 2; Part Class: Resistors; Price: 0; RoHS Compliant: Yes
R252 = RES_30.1K_OHM_1%_1_16W_0402_SMD
R285 R286 R290 = RESISTOR: RES - 200K OHM, 1/16W, 1%, 0402 SMD; Altera Part No.: P02-14020R; Item Num: P02-15992R; Lead Free Status: No; Manufacturer: Panasonic; Manufacturer Part Num: ERJ-2RKF2003X; Num Pins: 2; Part Class: RESISTORS; Price: 0; RoHS Compliant: Yes; Tolerance: 1%
R315 = RESISTOR: RES SMD 51 OHM 5% 1/10W 0603 0402 SMD; Altera Part No.: P02-14020R; Item Num: P02-17771R; Lead Free Status: Yes; Manufacturer: Yageo; Manufacturer Part Num: RC0603JR-0751RL; Num Pins: 2; Part Class: RESISTORS; Price: 0; RoHS Compliant: Yes; Tolerance: 5%
TP3-TP6 = T_POINT_R
U21 = EN5329_5339QI_0: REG - 3A LOW PROFILE SYNC BUCK DC-DC, VIN 2.4 - 5.5V, 24-QFN; Item Num: P05-18753R; Manufacturer: Enpirion; Part Class: Regulators; RoHS Compliant: Yes
U19 U22 = EP5348UI_0: REGULATOR - DC/DC, 400MA POWERSOC SYNC BUCK, INTEGRATED INDUCTOR, VIN 2.5-5.5V, 14-PIN UQFN; Item Num: P05-18760R; Manufacturer: Enpirion
C106 = CAP: CAP - CERAMIC 10UF 10V 10% X5R 0805; AGILE_LINK: http://sj-agile9app/Agile/PLMServlet?action=OpenEmailObject&classid=10000&objid=260383822; Item Num: P03-15049R; LIFECYCLE_PHASE: Active; Lead Free Status: Lead Free; MFR_LIFECYCLE: Active; Manufacturer: Panasonic; Manufacturer Part Num: ECJ-2FB1A106K; Num Pins: 2; PART_SUBCLASS: CAPACITORS; RATED_VOLTAGE: 10V; RoHS Compliant: RoHS Compliant; TOLERANCE: +/-10%
C217 C218 = CAP: CAP - CER 47UF, 10V, 20%, X5R, +/-20%, 0805; AGILE_LINK: http://sj-agile9app/Agile/PLMServlet?action=OpenEmailObject&classid=10000&objid=260383822; CAPACITANCE: 47uF; Item Num: P03-17686R; LIFECYCLE_PHASE: Active; Lead Free Status: Lead Free; MFR_LIFECYCLE: Active; Manufacturer: TDK Electronics; Manufacturer Part Num: C2012X5R1A476M125AC; Num Pins: 2; PART_SUBCLASS: CAPACITORS; RATED_VOLTAGE: 10V; RoHS Compliant: RoHS Compliant; TOLERANCE: +/-20%
C251 = CAP: CAP CER 2.2UF 10V 10% X5R 0402; AGILE_LINK: http://sj-agile9app/Agile/PLMServlet?action=OpenEmailObject&classid=10000&objid=256999866; Item Num: P03-17806R; LIFECYCLE_PHASE: Active; Lead Free Status: Lead Free; MFR_LIFECYCLE: Active; Manufacturer: Murata; Manufacturer Part Num: GRM155R61A225KE95D; Num Pins: 2; PART_SUBCLASS: CAPACITORS; RATED_VOLTAGE: 10V; RoHS Compliant: RoHS Compliant; Supplier Part Num: 490-1545-1-ND; TOLERANCE: +/-10%
R236 = RESISTOR: RES 0.1 OHM 1% 1/2W 0805 SMD; Item Num: P02-17735R; Lead Free Status: Yes; Manufacturer: Panasonic; Manufacturer Part Num: ERJ6BWFR100V; Num Pins: 2; Part Class: Resistors; Price: 0; RoHS Compliant: Yes
R291 = RESISTOR: RES - 63.0K OHM 1/16W 1% 0402 SMD; Altera Part No.: P02-14020R; Item Num: P02-17630R; Lead Free Status: No; Manufacturer: Panasonic; Manufacturer Part Num: ERJ-2RKF6302X; Num Pins: 2; Part Class: RESISTORS; Price: 0; RoHS Compliant: Yes; Tolerance: 1%
U20 = EP5358xUI: REGULATOR - DC/DC  1.8-3.3V 2W; Item Num: P05-18741R; Manufacturer: Enpirion; Part Class: Regulators; RoHS Compliant: Yes
R244 R245 = RES_2.0K_OHM_1_16W_1%_0402_SMD
U23 = N25Q00AA13GSF40F_1: MEM -SERIAL NOR, QUAD I/O, 512MB; Item Num: P01-17834R; Lead Free Status: Yes; Manufacturer: Micron; Num Pins: 16; Part Class: ICs; RoHS Compliant: Yes

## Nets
1.2V_CORE: C221.1 C222.1 C223.1 C224.2 C225.2 C226.2 C227.2 C228.2 C229.2 C230.2 C231.2 L8.1 R238.2 U1.J7(VCCINT) U1.K11(VCC) U1.K13(VCC) U1.L10(VCC) U1.L11(VCC) U1.L12(VCC) U1.M11(VCC) U1.M12(VCC) U1.M13(VCC) U1.N10(VCC) U1.N12(VCC)
1.2V_CORE_ENABLE: C174.1 R252.1 R283.1 U21.18(ENABLE)
1.2V_CORE_POK: R239.1 U21.17(POK) ; also on sheet 15
1.2V_CORE_SENSE: C112.2 C113.1 C114.1 C116.1 C248.1 C249.1 R238.1 R240.2 U21.4(VOUT) U21.5(VOUT) U21.6(VOUT) U21.7(VOUT)
1.2V_CORE_VFB: C112.1 R240.1 R243.2 U21.14(VFB)
1.2V_VCCD_PLL: C121.1 C122.1 C145.2 C146.2 C147.2 C148.2 L8.2 U1.G7(VCCD_PLL3) U1.G16(VCCD_PLL2) U1.T7(VCCD_PLL1) U1.U16(VCCD_PLL4)
1.2V_VCCIO: C118.1 C149.2 C194.1 C208.2 C209.1 C232.1 C233.2 C234.2 C235.2 C236.2 C250.1 R285.2 R315.2 U1.H16(VCCIO6) U1.J17(VCCIO6) U1.K16(VCCIO6) U1.K17(VCCIO6) U1.L16(VCCIO6) U1.M17(VCCIO6) U1.N16(VCCIO5) U1.N17(VCCIO6) U1.P16(VCCIO5) U1.R16(VCCIO5) U1.R17(VCCIO5) U1.T17(VCCIO5) U22.6(VOUT) U22.7(VOUT) ; also on sheet 6 10 18
1.2V_VCCIO_ENABLE: C119.1 R241.1 R242.1 U22.10(ENABLE)
1.2V_VCCIO_VFB: C208.1 R285.1 R286.2 U22.4(VFB)
1.8V: C105.1 C106.1 C107.1 C196.1 C197.1 C217.1 C218.1 C219.1 R235.1 R241.2 R279.2 U1.N6(VCCIO2) U1.N7(VCCIO2) U1.P7(VCCIO2) U1.R6(VCCIO2) U20.7(VOUT) U20.8(VOUT) ; also on sheet 4 10 11 12 14 19
1.8V_ENABLE: C176.1 R257.2 U20.12(ENABLE)
2.5V: C144.2 C211.1 C213.1 C216.2 C239.2 C251.1 R236.1 R283.2 R290.2 U1.T9(VCCIO3) U1.T10(VCCIO3) U1.T11(VCCIO3) U1.T12(VCCIO4) U1.T13(VCCIO4) U1.U8(VCCIO3) U1.U9(VCCIO3) U1.U11(VCCIO4) U1.U12(VCCIO4) U1.U14(VCCIO4) U19.6(VOUT) U19.7(VOUT) ; also on sheet 9 16 17 18 19
2.5V_CORE: L7.1 R236.2
2.5V_ENABLE: C175.1 R255.1 R282.1 U19.10(ENABLE)
2.5V_VCCA: C108.1 C109.1 C124.2 C206.2 C237.2 C238.2 L7.2 R267.2 U1.H7(VCCA_ADC) U1.H8(VCCA3) U1.H15(VCCA2) U1.R8(VCCA1) U1.T15(VCCA4)
3.3V: C91.1 C92.1 C93.1 C155.2 C156.2 C169.2 C170.1 R223.2 R239.2 R244.1 R245.1 R281.2 U1.F9(VCCIO8) U1.F11(VCCIO8) U1.F12(VCCIO7) U1.F14(VCCIO7) U1.G10(VCCIO8) U1.G11(VCCIO8) U1.G12(VCCIO7) U1.G13(VCCIO7) U1.G14(VCCIO7) U1.K7(VCCIO1A) U1.L6(VCCIO1A) U1.L7(VCCIO1B) U1.M6(VCCIO1B) U17.4(VOUT) U17.5(VOUT) U17.6(VOUT) U17.7(VOUT) U23.2(VCC) ; also on sheet 9 11 12 13 14 15 16 17 18 19
3.3V_EN: C207.1 R279.1 R280.1 R284.2 U17.18(ENABLE)
3.3V_POK: R281.1 R282.2 U17.17(POK)
3.3V_VFB: C91.2 R223.1 R229.2 U17.14(VFB)
5V: J11.2 R253.1 R254.1 R258.1 R260.1 R280.2 R289.1 R292.2 R293.1 ; also on sheet 14 18
5V_DCIN: J10.2 R217.1 R222.2 R224.2 U18.2(VDD) V1.2(SNS)
5V_FB: R226.1 R233.2 U18.12(FB)
5V_GATE: R225.2 R231.2 U18.9(GATE)
5V_IMON: R232.2 U18.13(IMON)
5V_MONITOR: C94.1 C95.2 J11.1 R226.2 R227.2 R228.1 R292.1 U16.1(S1) U16.2(S2) U16.3(S3) U18.8(SOURCE)
5V_N: U18.15(SENSE-) V2.1(RSNS)
5V_OV: R224.1 R230.2 U18.4(OV)
5V_P: U18.16(SENSE+) V1.1(RSNS)
5V_PG: R227.1 U18.10(PG)
5V_R1.2CORE: C111.1 C120.1 R252.2 R253.2 U21.10(TST2) U21.11(TST1) U21.12(TST0) U21.16(AVIN) U21.19(PVIN) U21.20(PVIN)
5V_R1.2VCCIO: C115.1 C210.2 R242.2 R254.2 U22.11(AVIN) U22.12(PVIN)
5V_R1.8: C104.1 R257.1 R258.2 U20.9(VS2) U20.10(VS1) U20.11(VS0) U20.13(AVIN) U20.14(PVIN)
5V_R2.5: C212.2 C215.1 R255.2 R289.2 U19.11(AVIN) U19.12(PVIN)
5V_R3.3: C90.1 C96.1 R260.2 U17.10(TST2) U17.11(TST1) U17.12(TST0) U17.16(AVIN) U17.19(PVIN) U17.20(PVIN)
5V_UV: R264.2 U18.3(UV) U18.11(/FLT)
GND: C90.2 C92.2 C93.2 C94.2 C95.1 C96.2 C97.2 C98.1 C99.2 C104.2 C106.2 C107.2 C108.2 C109.2 C111.2 C113.2 C114.2 C115.2 C116.2 C118.2 C119.2 C120.2 C121.2 C122.2 C124.1 C144.1 C145.1 C146.1 C147.1 C148.1 C149.1 C155.1 C156.1 C169.1 C170.2 C174.2 C175.2 C176.2 C194.2 C196.2 C197.2 C206.1 C207.2 C209.2 C210.1 C211.2 C212.1 C213.2 C215.2 C217.2 C218.2 C219.2 C220.2 C221.2 C222.2 C223.2 C224.1 C225.1 C226.1 C227.1 C228.1 C229.1 C230.1 C231.1 C232.2 C233.1 C234.1 C235.1 C236.1 C237.1 C238.1 C239.1 C248.2 C249.2 C250.2 C251.2 J10.1 J10.3 R221.1 R228.2 R229.1 R230.1 R232.1 R233.1 R243.1 R284.1 R286.1 R291.1 R315.1 SW3.1(NO1) SW3.6(NO2) TP1.1(TP) TP2.1(TP) TP3.1(TP) TP4.1(TP) TP5.1(TP) TP6.1(TP) U1.A1(GND) U1.A22(GND) U1.AA4(GND) U1.AA18(GND) U1.AB1(GND) U1.AB22(GND) U1.B6(GND) U1.B9(GND) U1.B13(GND) U1.B18(GND) U1.D4(GND) U1.D11(GND) U1.D16(GND) U1.D20(GND) U1.E2(GND) U1.E5(NC1) U1.E7(GND) U1.F6(NC2) U1.F10(GND) U1.F13(GND) U1.G5(ANAIN1) U1.G6(GND) U1.G8(GND) U1.G15(GND) U1.G18(GND) U1.G21(GND) U1.H5(REFGND) U1.J2(GND) U1.J5(ANAIN2) U1.J6(GND) U1.J16(GND) U1.J19(GND) U1.K3(GND) U1.K10(GND) U1.K12(GND) U1.L5(GND) U1.L13(GND) U1.L17(GND) U1.L21(GND) U1.M7(GND) U1.M10(GND) U1.M16(GND) U1.M19(GND) U1.N11(GND) U1.N13(GND) U1.P2(GND) U1.P6(GND) U1.P17(GND) U1.R19(GND) U1.R21(GND) U1.T4(GND) U1.T8(GND) U1.T14(GND) U1.T16(GND) U1.U10(GND) U1.U13(GND) U1.V2(GND) U1.V6(GND) U1.V19(GND) U1.W21(GND) U1.Y9(GND) U1.Y12(GND) U1.Y15(GND) U17.2(PGND) U17.3(PGND) U17.8(PGND) U17.9(PGND) U17.15(AGND) U17.25(PGND) U17.26(PGND) U18.7(GND) U19.2(PGND) U19.5(AGND) U20.2(PGND) U20.3(PGND) U20.6(AGND) U21.2(PGND) U21.3(PGND) U21.8(PGND) U21.9(PGND) U21.15(AGND) U21.25(PGND) U21.26(PGND) U22.2(PGND) U22.5(AGND) U23.10(VSS) ; also on sheet 4 6 8 9 10 11 12 13 14 15 16 17 18 19
VBUS_5V: C220.1 J11.3 R293.2 ; also on sheet 15
ADC_VREF: R267.1 U1.H6(ADC_VREF)
FLASH_CLK: U23.16(C) ; also on sheet 7
FLASH_CSn: R245.2 U23.7(S#) ; also on sheet 7
FLASH_D0: U23.15(DQ0) ; also on sheet 7
FLASH_D1: U23.8(DQ1) ; also on sheet 7
FLASH_D2: U23.9(DQ2/VPP/W#) ; also on sheet 7
FLASH_D3: U23.1(DQ3/HOLD#) ; also on sheet 7
FLASH_RESETn: R244.2 U23.3(RESET) ; also on sheet 7 15
N16938690: R217.2 SW3.2(NC1) SW3.5(NC2)
N16938718: R221.2 R264.1 SW3.3(COMMON1) SW3.4(COMMON2)
N16938802: C97.1 U18.5(TIMER)
N16938806: C99.1 U18.6(INTVCC)
N16938884: C98.2 R231.1
N16939009: R225.1 U16.4(G)
N16939055: R222.1 U16.5(D) V2.2(SNS)
N16993273: C105.2 R235.2 U20.5(VSENSE)
N17581797: C216.1 R290.1 R291.2 U19.4(VFB)

Not connected (* = marked no-connect by the designer): U1 L3(DNU)*; U17 1(NC(SW)0)* 13(NC)* 21(NC(SW)1)* 22(NC(SW)2)* 23(NC(SW)3)* 24(NC(SW)4)*; U18 1(NC)* 14(ISET)*; U19 1(NC(SW)0)* 3(NC0)* 8(NC1)* 9(NC2)* 13(NC(SW)1)* 14(NC(SW)2)*; U20 1(NC1)* 4(VFB/NC4)* 15(NC15)* 16(NC16)*; U21 1(NC(SW)0)* 13(NC)* 21(NC(SW)1)* 22(NC(SW)2)* 23(NC(SW)3)* 24(NC(SW)4)*; U22 1(NC(SW)0)* 3(NC0)* 8(NC1)* 9(NC2)* 13(NC(SW)1)* 14(NC(SW)2)*; U23 4(DNU2) 5(DNU3) 6(DNU4) 11(DNU5) 12(DNU6) 13(DNU7) 14(DNU8)

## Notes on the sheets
sheet 20
- HOT SWAP and POWER 3.3V
- 5V
  DC Input
- CAUTION:
  When NOT using jumpers,
  solder R292 for power input from DC Jack,
  or solder R293 for USB power.
  SOLDER ONLY ONE POWER OPTION,
  AND SUGGEST NOT TO USE WITH JUMPER.
- EN5329
- POWER 3.3V
- Hot Swap for DC Plug
- Notes:
  Place C90 near PVIN pin.
- Notes:
  Place C91, R223 and R229
  near EN5329QI VFB pin.
- Notes:
  Place C96 near AVIN pin.
- Hot Swap Controller Circuit
- Altera Corporation, 301, Bibo Rd #888, Shanghai, China, 201203
- Copyright (c) 2015, Altera Corporation. All Rights Reserved.
sheet 21
- POWER 2.5V & 1.8V
- POWER 2.5V
- EN5329
- Notes:
  Place caps near EP5348UI.
- Notes:
  Place caps near EP5348UI.
- POWER 1.8V
- POWER 2.5V_VCCA
- Note:
  Possible adjustment within
  15% VID setting by parallel
  RC combination.
- Notes:
  Place C104 close to EP5358.
- Notes:
  Place caps near EP5358HUI.
- Altera Corporation, 301, Bibo Rd #888, Shanghai, China, 201203
- Copyright (c) 2015, Altera Corporation. All Rights Reserved.
sheet 22
- POWER 1.2V
- POWER 1.2V_CORE
- Notes:
  Place C112, R240 and R243
  near EN5329QI VFB pin.
- EN5339
- Notes:
  Place C111 close to PVIN pin.
- Place a 1μF cap
  from the AVIN pin
  to AGND pin.
- POWER 1.2V_VCCIO
- POWER 1.2V_VCCD_PLL
- Notes:
  Place caps near EP5348UI.
- Notes:
  Place caps near EP5348UI.
- Notes:
  Place the 10uF capacitor close to ferrite bead.
  Place the 0.1uF capacitor close to MAX 10 pin.
- Altera Corporation, 301, Bibo Rd #888, Shanghai, China, 201203
- Copyright (c) 2015, Altera Corporation. All Rights Reserved.
sheet 23
- MAX 10 POWER & GROUND
- Note:
  According to MAX 10 pin
  connection guideline
  PCG-01018-1.2,
  "Tie the VCCINT pin to any
  1.2V power domain if you
  are not using ADC."
  Therefore, connect VCCINT
  to 1.2V_CORE for DC or DF
  production device migration.
- Note:
  According to MAX 10 pin
  connection guideline
  PCG-01018-1.2,
  "Tie the VCCA_ADC pin
  to any 2.5V power domain
  if you are not using ADC,
  and do not tie the VCCA_ADC
  pin to GND."
  Therefore, connect VCCA_ADC
  to 2.5V_CORE for DC or DF
  production device migration.
- Note:
  For ES device, connect ADC_VREF to NC
  when not using external voltage reference.
  For DC/DF production device, ADC_VREF
  pin is migrated to VCCA according to MAX
  10 Errata.
- Altera Corporation, 301, Bibo Rd #888, Shanghai, China, 201203
- Copyright (c) 2015, Altera Corporation. All Rights Reserved.
sheet 24
- DECOUPLING
- Notes:
  Place 100uF near LPDDR2 or between LPDDR2 and MAX10.
  Place 1.0uF and 0.1uF capacitors close to MAX 10 VCCIO5 and VCCIO6 pins.
- Notes:
  Place capacitor near MAX 10 pins.
- Notes:
  Place a 0.1uF capacitor close to each MAX 10 VCCD pin.
- Notes:
  Place these capacitors close to MAX 10 VCCIO3 and VCCIO4 pins.
  Place one 0.1uF close to MAX 10 VCCA_ADC pin.
- Notes:
  Place these capacitors close to each MAX 10 VCCA pin.
- Notes:
  Place these capacitors close to MAX 10 VCCIO7 and VCCIO8 pins.
- Notes:
  Place these capacitors close to MAX 10 VCCIO2.
- Altera Corporation, 301, Bibo Rd #888, Shanghai, China, 201203
- Copyright (c) 2015, Altera Corporation. All Rights Reserved.
sheet 25
- QSPI FLASH
- Notes:
  Place the two caps near QSPI flash
- QSPI FLASH
- Altera Corporation, 301, Bibo Rd #888, Shanghai, China, 201203
- Copyright (c) 2015, Altera Corporation. All Rights Reserved.
